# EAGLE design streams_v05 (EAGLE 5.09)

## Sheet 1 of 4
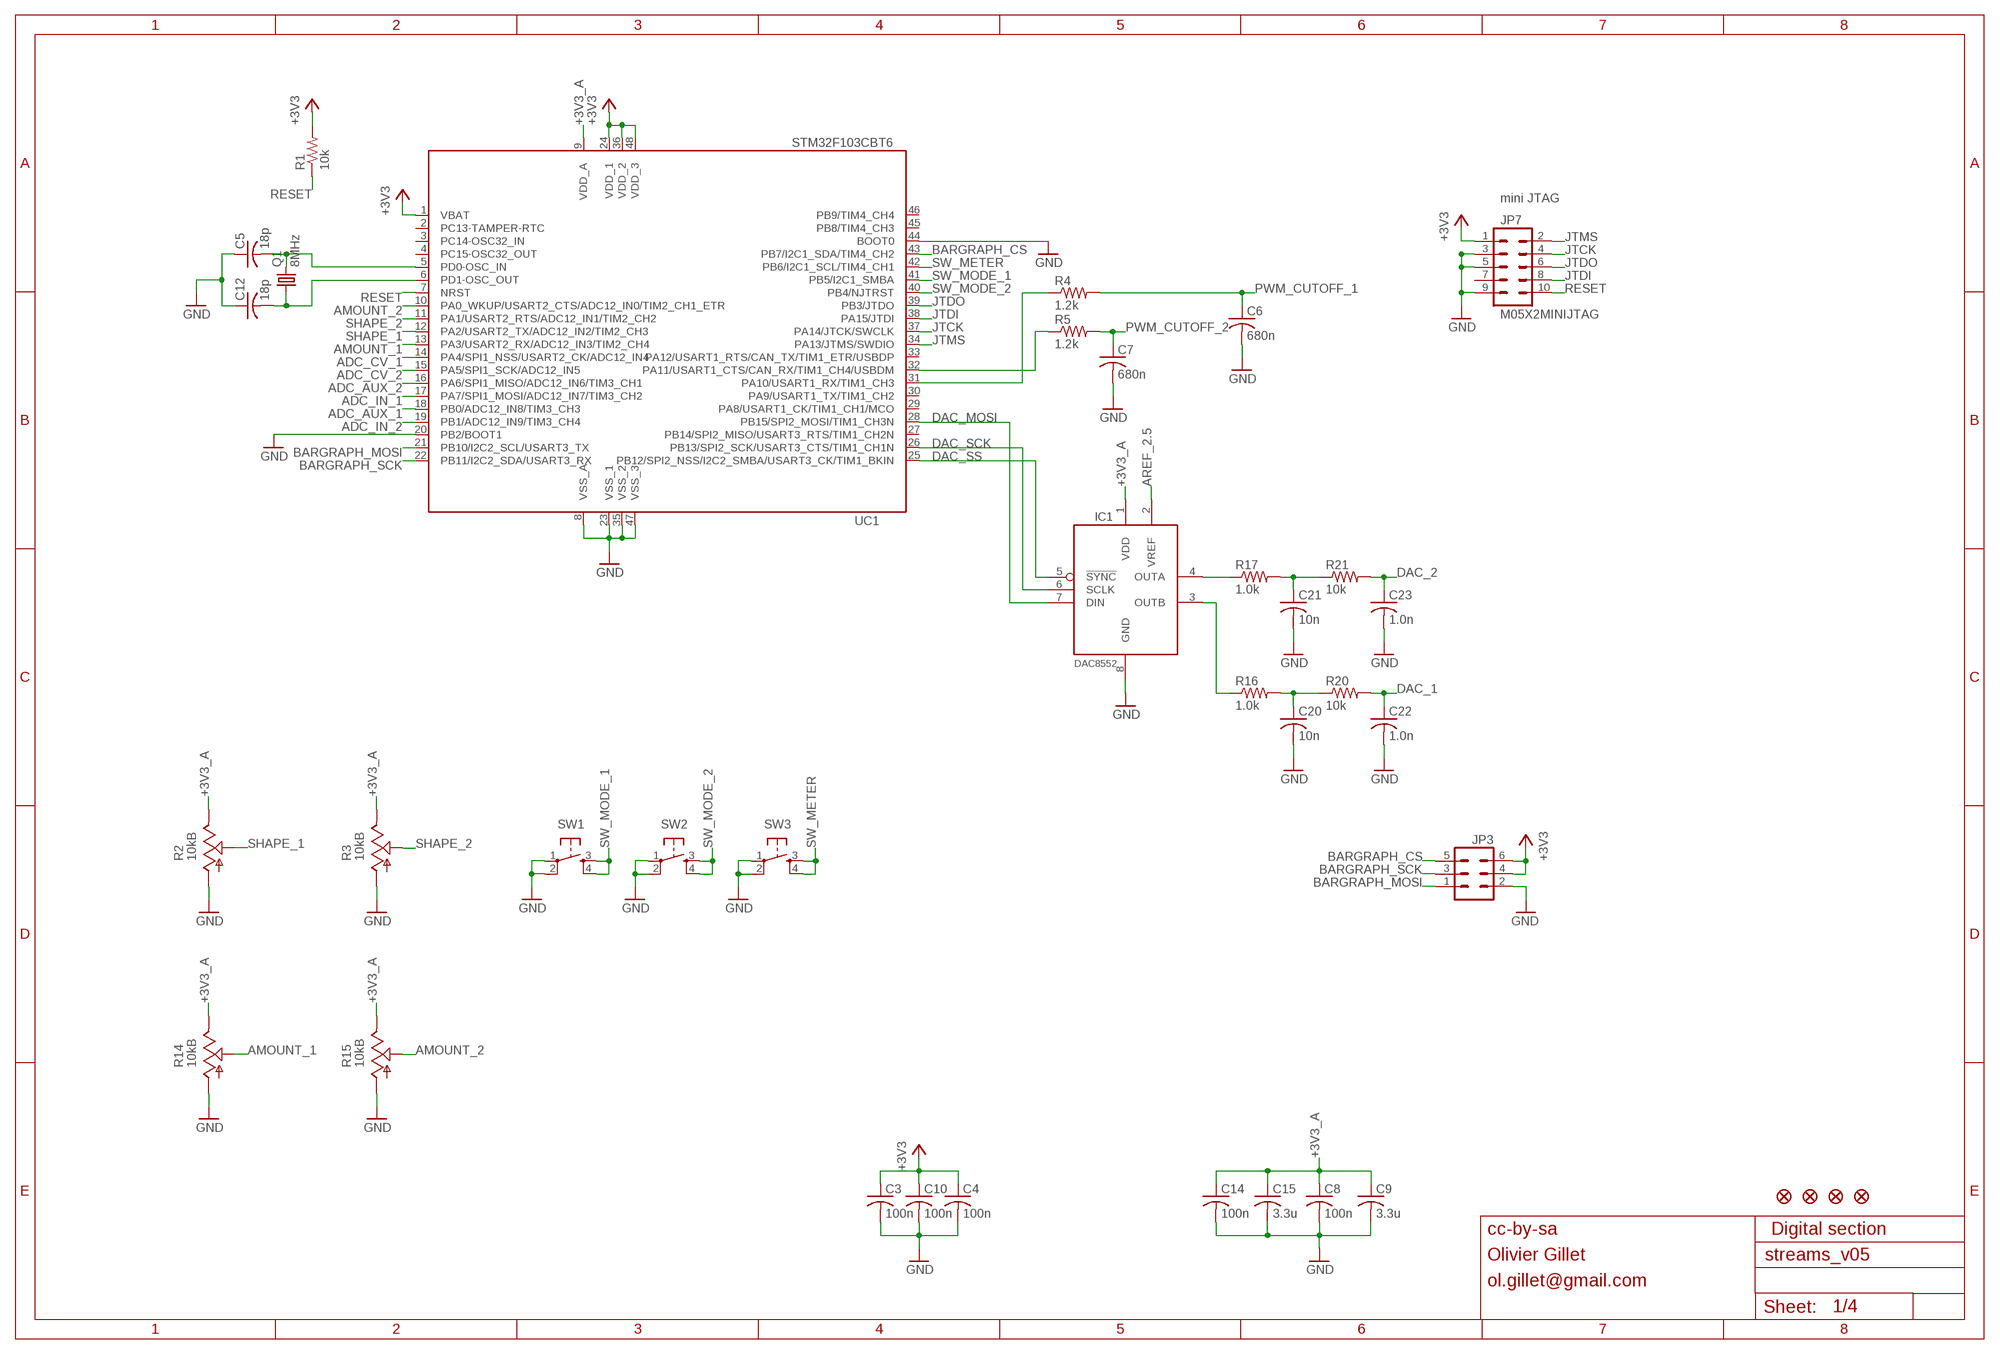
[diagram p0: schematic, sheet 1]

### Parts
C3  100n  C-USC0603  [C0603]
C4  100n  C-USC0603  [C0603]
C5  18p  C-USC0603  [C0603]
C6  680n  C-USC0603  [C0603]
C7  680n  C-USC0603  [C0603]
C8  100n  C-USC0603  [C0603]
C9  3.3u  C-USC0603  [C0603]
C10  100n  C-USC0603  [C0603]
C12  18p  C-USC0603  [C0603]
C14  100n  C-USC0603  [C0603]
C15  3.3u  C-USC0603  [C0603]
C20  10n  C-USC0603  [C0603]
C21  10n  C-USC0603  [C0603]
C22  1.0n  C-USC0603  [C0603]
C23  1.0n  C-USC0603  [C0603]
IC1  DAC8552  [MSOP-8]
JP1  FIDUCIAL1X2  [FIDUCIAL-1X2]
JP2  FIDUCIAL1X2  [FIDUCIAL-1X2]
JP3  M03X2BOTTOM  [2X3_BOTTOM]
JP4  FIDUCIAL1X2  [FIDUCIAL-1X2]
JP5  FIDUCIAL1X2  [FIDUCIAL-1X2]
JP7  M05X2MINIJTAG  [2X5-1.27]
Q1  8MHz  CRYSTALHC49UP  [HC49UP]
R1  10k  R-US_R0603  [R0603]
R2  10kB  POT_USVERTICAL_PS  [ALPS_POT_VERTICAL_PS]
R3  10kB  POT_USVERTICAL_PS  [ALPS_POT_VERTICAL_PS]
R4  1.2k  R-US_R0603  [R0603]
R5  1.2k  R-US_R0603  [R0603]
R14  10kB  POT_USVERTICAL_PS  [ALPS_POT_VERTICAL_PS]
R15  10kB  POT_USVERTICAL_PS  [ALPS_POT_VERTICAL_PS]
R16  1.0k  R-US_R0603  [R0603]
R17  1.0k  R-US_R0603  [R0603]
R20  10k  R-US_R0603  [R0603]
R21  10k  R-US_R0603  [R0603]
SW1  TAC_SWITCHPTH  [TACTILE-PTH]
SW2  TAC_SWITCHPTH  [TACTILE-PTH]
SW3  TAC_SWITCHPTH  [TACTILE-PTH]
UC1  STM32F103CBT6  STM32F103CB  [LQFP48]

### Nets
+3V3: C3.1 C4.1 C10.1 JP3.4 JP3.6 JP7.1 R1.2 UC1.1(VBAT) UC1.24(VDD_1) UC1.36(VDD_2) UC1.48(VDD_3) ; also sheet 4
+3V3_A: C8.1 C9.1 C14.1 C15.1 IC1.1(VDD) R2.P$1(E) R3.P$1(E) R14.P$1(E) R15.P$1(E) UC1.9(VDD_A) ; also sheet 2,3,4
ADC_AUX_1: UC1.18(PB0/ADC12_IN8/TIM3_CH3) ; also sheet 2
ADC_AUX_2: UC1.16(PA6/SPI1_MISO/ADC12_IN6/TIM3_CH1) ; also sheet 3
ADC_CV_1: UC1.14(PA4/SPI1_NSS/USART2_CK/ADC12_IN4) ; also sheet 2
ADC_CV_2: UC1.15(PA5/SPI1_SCK/ADC12_IN5) ; also sheet 3
ADC_IN_1: UC1.17(PA7/SPI1_MOSI/ADC12_IN7/TIM3_CH2) ; also sheet 2
ADC_IN_2: UC1.19(PB1/ADC12_IN9/TIM3_CH4) ; also sheet 3
AMOUNT_1: R14.P$2(S) UC1.13(PA3/USART2_RX/ADC12_IN3/TIM2_CH4)
AMOUNT_2: R15.P$2(S) UC1.10(PA0_WKUP/USART2_CTS/ADC12_IN0/TIM2_CH1_ETR)
AREF_2.5: IC1.2(VREF) ; also sheet 4
BARGRAPH_CS: JP3.5 UC1.43(PB7/I2C1_SDA/TIM4_CH2)
BARGRAPH_MOSI: JP3.1 UC1.21(PB10/I2C2_SCL/USART3_TX)
BARGRAPH_SCK: JP3.3 UC1.22(PB11/I2C2_SDA/USART3_RX)
DAC_1: C22.1 R20.2 ; also sheet 2
DAC_2: C23.1 R21.2 ; also sheet 3
DAC_MOSI: IC1.7(DIN) UC1.28(PB15/SPI2_MOSI/TIM1_CH3N)
DAC_SCK: IC1.6(SCLK) UC1.26(PB13/SPI2_SCK/USART3_CTS/TIM1_CH1N)
DAC_SS: IC1.5(!SYNC) UC1.25(PB12/SPI2_NSS/I2C2_SMBA/USART3_CK/TIM1_BKIN)
GND: C3.2 C4.2 C5.1 C6.2 C7.2 C8.2 C9.2 C10.2 C12.1 C14.2 C15.2 C20.2 C21.2 C22.2 C23.2 IC1.8(GND) JP3.2 JP7.3 JP7.5 JP7.9 R2.P$3(A) R3.P$3(A) R14.P$3(A) R15.P$3(A) SW1.1 SW1.2 SW2.1 SW2.2 SW3.1 SW3.2 UC1.8(VSS_A) UC1.20(PB2/BOOT1) UC1.23(VSS_1) UC1.35(VSS_2) UC1.44(BOOT0) UC1.47(VSS_3) ; also sheet 2,3,4
JTCK: JP7.4 UC1.37(PA14/JTCK/SWCLK)
JTDI: JP7.8 UC1.38(PA15/JTDI)
JTDO: JP7.6 UC1.39(PB3/JTDO)
JTMS: JP7.2 UC1.34(PA13/JTMS/SWDIO)
N$7: C5.2 Q1.2 UC1.5(PD0-OSC_IN)
N$8: C12.2 Q1.1 UC1.6(PD1-OSC_OUT)
N$70: IC1.4(OUTA) R17.1
N$72: IC1.3(OUTB) R16.1
N$73: C21.1 R17.2 R21.1
N$74: C20.1 R16.2 R20.1
N$90: R5.1 UC1.32(PA11/USART1_CTS/CAN_RX/TIM1_CH4/USBDM)
N$93: R4.1 UC1.31(PA10/USART1_RX/TIM1_CH3)
PWM_CUTOFF_1: C6.1 R4.2 ; also sheet 2
PWM_CUTOFF_2: C7.1 R5.2 ; also sheet 3
RESET: JP7.10 R1.1 UC1.7(NRST)
SHAPE_1: R2.P$2(S) UC1.12(PA2/USART2_TX/ADC12_IN2/TIM2_CH3)
SHAPE_2: R3.P$2(S) UC1.11(PA1/USART2_RTS/ADC12_IN1/TIM2_CH2)
SW_METER: SW3.3 SW3.4 UC1.42(PB6/I2C1_SCL/TIM4_CH1)
SW_MODE_1: SW1.3 SW1.4 UC1.41(PB5/I2C1_SMBA)
SW_MODE_2: SW2.3 SW2.4 UC1.40(PB4/NJTRST)
Unconnected: JP7.7 UC1.2(PC13-TAMPER-RTC) UC1.3(PC14-OSC32_IN) UC1.4(PC15-OSC32_OUT) UC1.27(PB14/SPI2_MISO/USART3_RTS/TIM1_CH2N) UC1.29(PA8/USART1_CK/TIM1_CH1/MCO) UC1.30(PA9/USART1_TX/TIM1_CH2) UC1.33(PA12/USART1_RTS/CAN_TX/TIM1_ETR/USBDP) UC1.45(PB8/TIM4_CH3) UC1.46(PB9/TIM4_CH4)

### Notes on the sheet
- mini JTAG
- cc-by-sa | Digital section
- Olivier Gillet
- ol.gillet@gmail.com

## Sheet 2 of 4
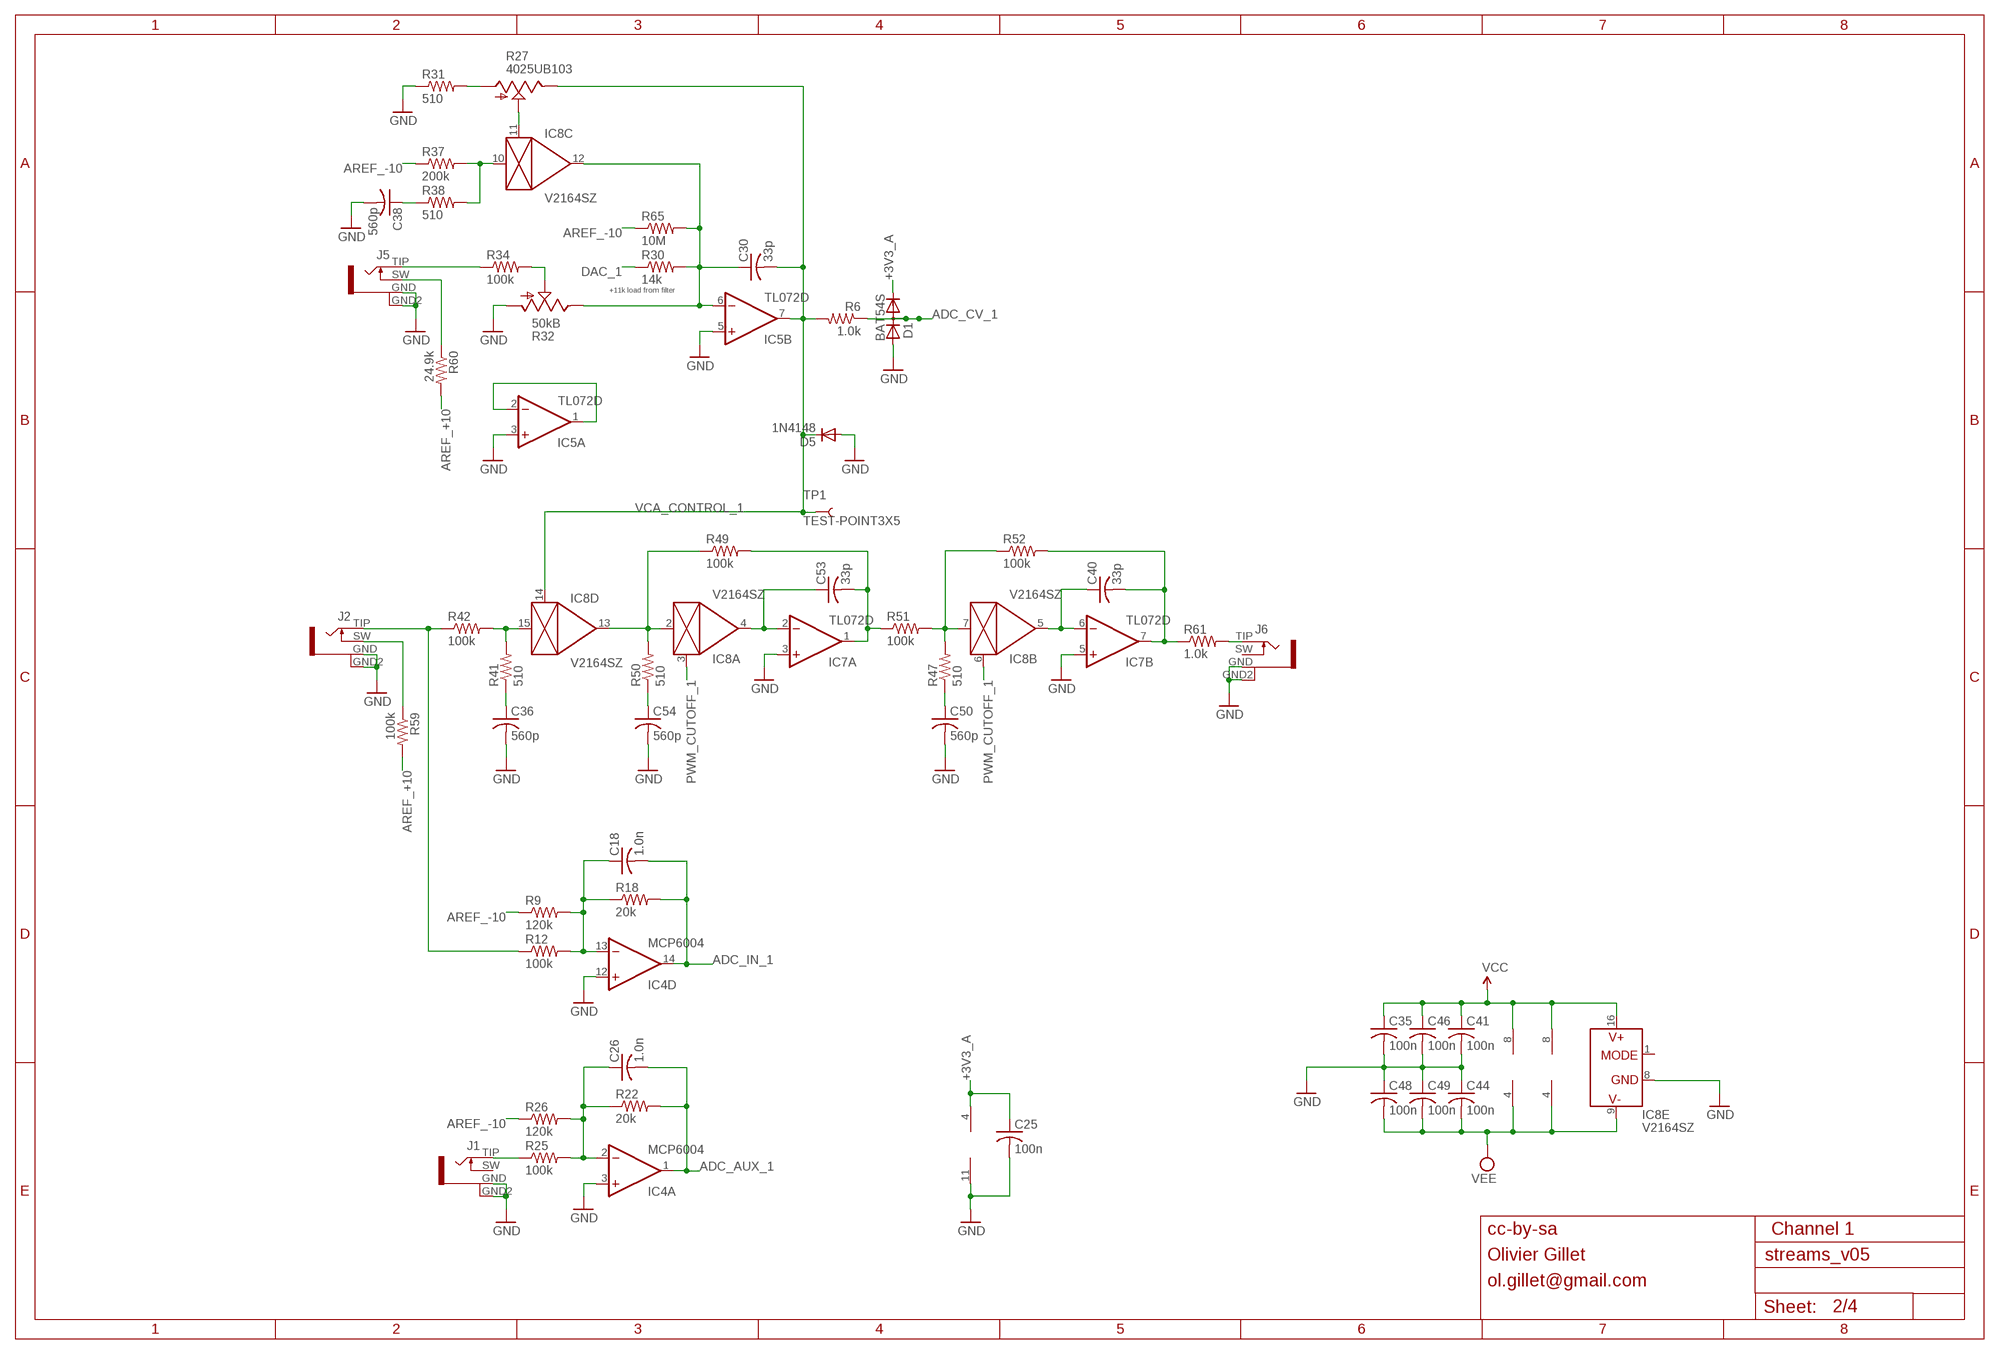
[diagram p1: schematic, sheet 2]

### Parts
C18  1.0n  C-USC0603  [C0603]
C25  100n  C-USC0603  [C0603]
C26  1.0n  C-USC0603  [C0603]
C30  33p  C-USC0603  [C0603]
C35  100n  C-USC0603  [C0603]
C36  560p  C-USC0603  [C0603]
C38  560p  C-USC0603  [C0603]
C40  33p  C-USC0603  [C0603]
C41  100n  C-USC0603  [C0603]
C44  100n  C-USC0603  [C0603]
C46  100n  C-USC0603  [C0603]
C48  100n  C-USC0603  [C0603]
C49  100n  C-USC0603  [C0603]
C50  560p  C-USC0603  [C0603]
C53  33p  C-USC0603  [C0603]
C54  560p  C-USC0603  [C0603]
D1  BAT54S  DIODE_2CACA-SOT23  [SOT23]
D5  1N4148  DIODE-SOD323-W  [SOD323-W]
IC4  MCP6004  TL074D  [SO14]
IC5  TL072D  [SO08]
IC7  TL072D  [SO08]
IC8  V2164SZ  SSM2164S  [SOIC16N]
J1  PJ301WQP  [WQP_PJ_301BM_WIDER]
J2  PJ301WQP  [WQP_PJ_301BM_WIDER]
J5  PJ301WQP  [WQP_PJ_301BM_WIDER]
J6  PJ301WQP  [WQP_PJ_301BM_WIDER]
R6  1.0k  R-US_R0603  [R0603]
R9  120k  R-US_R0603  [R0603]
R12  100k  R-US_R0603  [R0603]
R18  20k  R-US_R0603  [R0603]
R22  20k  R-US_R0603  [R0603]
R25  100k  R-US_R0603  [R0603]
R26  120k  R-US_R0603  [R0603]
R27  4025UB103  POT_USVERTICAL  [ALPS_POT_VERTICAL]
R30  14k  R-US_R0603  [R0603]
R31  510  R-US_R0603  [R0603]
R32  50kB  POT_USVERTICAL_PS  [ALPS_POT_VERTICAL_PS]
R34  100k  R-US_R0603  [R0603]
R37  200k  R-US_R0603  [R0603]
R38  510  R-US_R0603  [R0603]
R41  510  R-US_R0603  [R0603]
R42  100k  R-US_R0603  [R0603]
R47  510  R-US_R0603  [R0603]
R49  100k  R-US_R0603  [R0603]
R50  510  R-US_R0603  [R0603]
R51  100k  R-US_R0603  [R0603]
R52  100k  R-US_R0603  [R0603]
R59  100k  R-US_R0603  [R0603]
R60  24.9k  R-US_R0603  [R0603]
R61  1.0k  R-US_R0603  [R0603]
R65  10M  R-US_R0603  [R0603]
TP1  TEST-POINT3X5  [PAD.03X.05]

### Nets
+3V3_A: C25.1 D1.2(C) IC4.4(P:V+) ; also sheet 1,3,4
ADC_AUX_1: C26.2 IC4.1(A:OUT) R22.2 ; also sheet 1
ADC_CV_1: D1.3(AC) R6.1 ; also sheet 1
ADC_IN_1: C18.2 IC4.14(D:OUT) R18.2 ; also sheet 1
AREF_+5: J2.SW R59.1
AREF_+10: R59.2 R60.2 ; also sheet 3,4
AREF_-10: R9.1 R26.1 R37.1 R65.1 ; also sheet 3,4
DAC_1: R30.1 ; also sheet 1
FB_CURRENT1: IC8.10(C:IN) R37.2 R38.2
FB_CURRENT2: IC8.15(D:IN) R41.2 R42.2
GND: C25.2 C35.2 C36.2 C38.2 C41.2 C44.1 C46.2 C48.1 C49.1 C50.2 C54.2 D1.1(A) D5.A IC4.3(A:+IN) IC4.11(P:V-) IC4.12(D:+IN) IC5.3(A:+IN) IC5.5(B:+IN) IC7.3(A:+IN) IC7.5(B:+IN) IC8.8(E:GND) J1.GND J1.GND2 J2.GND J2.GND2 J5.GND J5.GND2 J6.GND J6.GND2 R31.1 R32.P$3(A) ; also sheet 1,3,4
IN_1: J2.TIP R12.1 R42.1
N$1: R27.P$3(A) R31.2
N$2: C30.1 IC5.6(B:-IN) IC8.12(C:OUT) R30.2 R32.P$1(E) R65.2
N$5: C38.1 R38.1
N$10: C36.1 R41.1
N$11: IC5.1(A:OUT) IC5.2(A:-IN)
N$12: J5.SW R60.1
N$13: J5.TIP R34.1
N$15: IC8.11(C:CTRL) R27.P$2(S)
N$23: R32.P$2(S) R34.2
N$26: C40.1 IC7.6(B:-IN) IC8.5(B:OUT)
N$27: C40.2 IC7.7(B:OUT) R52.2 R61.1
N$51: IC8.2(A:IN) IC8.13(D:OUT) R49.1 R50.2
N$65: J1.TIP R25.1
N$68: C18.1 IC4.13(D:-IN) R9.2 R12.2 R18.1
N$69: C26.1 IC4.2(A:-IN) R22.1 R25.2 R26.2
N$79: C53.1 IC7.2(A:-IN) IC8.4(A:OUT)
N$83: C53.2 IC7.1(A:OUT) R49.2 R51.1
N$84: IC8.7(B:IN) R47.2 R51.2 R52.1
N$85: C54.1 R50.1
N$86: C50.1 R47.1
N$87: J6.TIP R61.2
PWM_CUTOFF_1: IC8.3(A:CTRL) IC8.6(B:CTRL) ; also sheet 1
VCA_CONTROL_1: C30.2 D5.C IC5.7(B:OUT) IC8.14(D:CTRL) R6.2 R27.P$1(E) TP1.P$1
VCC: C35.1 C41.1 C46.1 IC5.8(P:V+) IC7.8(P:V+) IC8.16(E:V+) ; also sheet 3,4
VEE: C44.2 C48.2 C49.2 IC5.4(P:V-) IC7.4(P:V-) IC8.9(E:V-) ; also sheet 3,4
Unconnected: IC8.1(E:MODE) J1.SW J6.SW

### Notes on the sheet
- +11k load from filter
- cc-by-sa | Channel 1
- Olivier Gillet
- ol.gillet@gmail.com

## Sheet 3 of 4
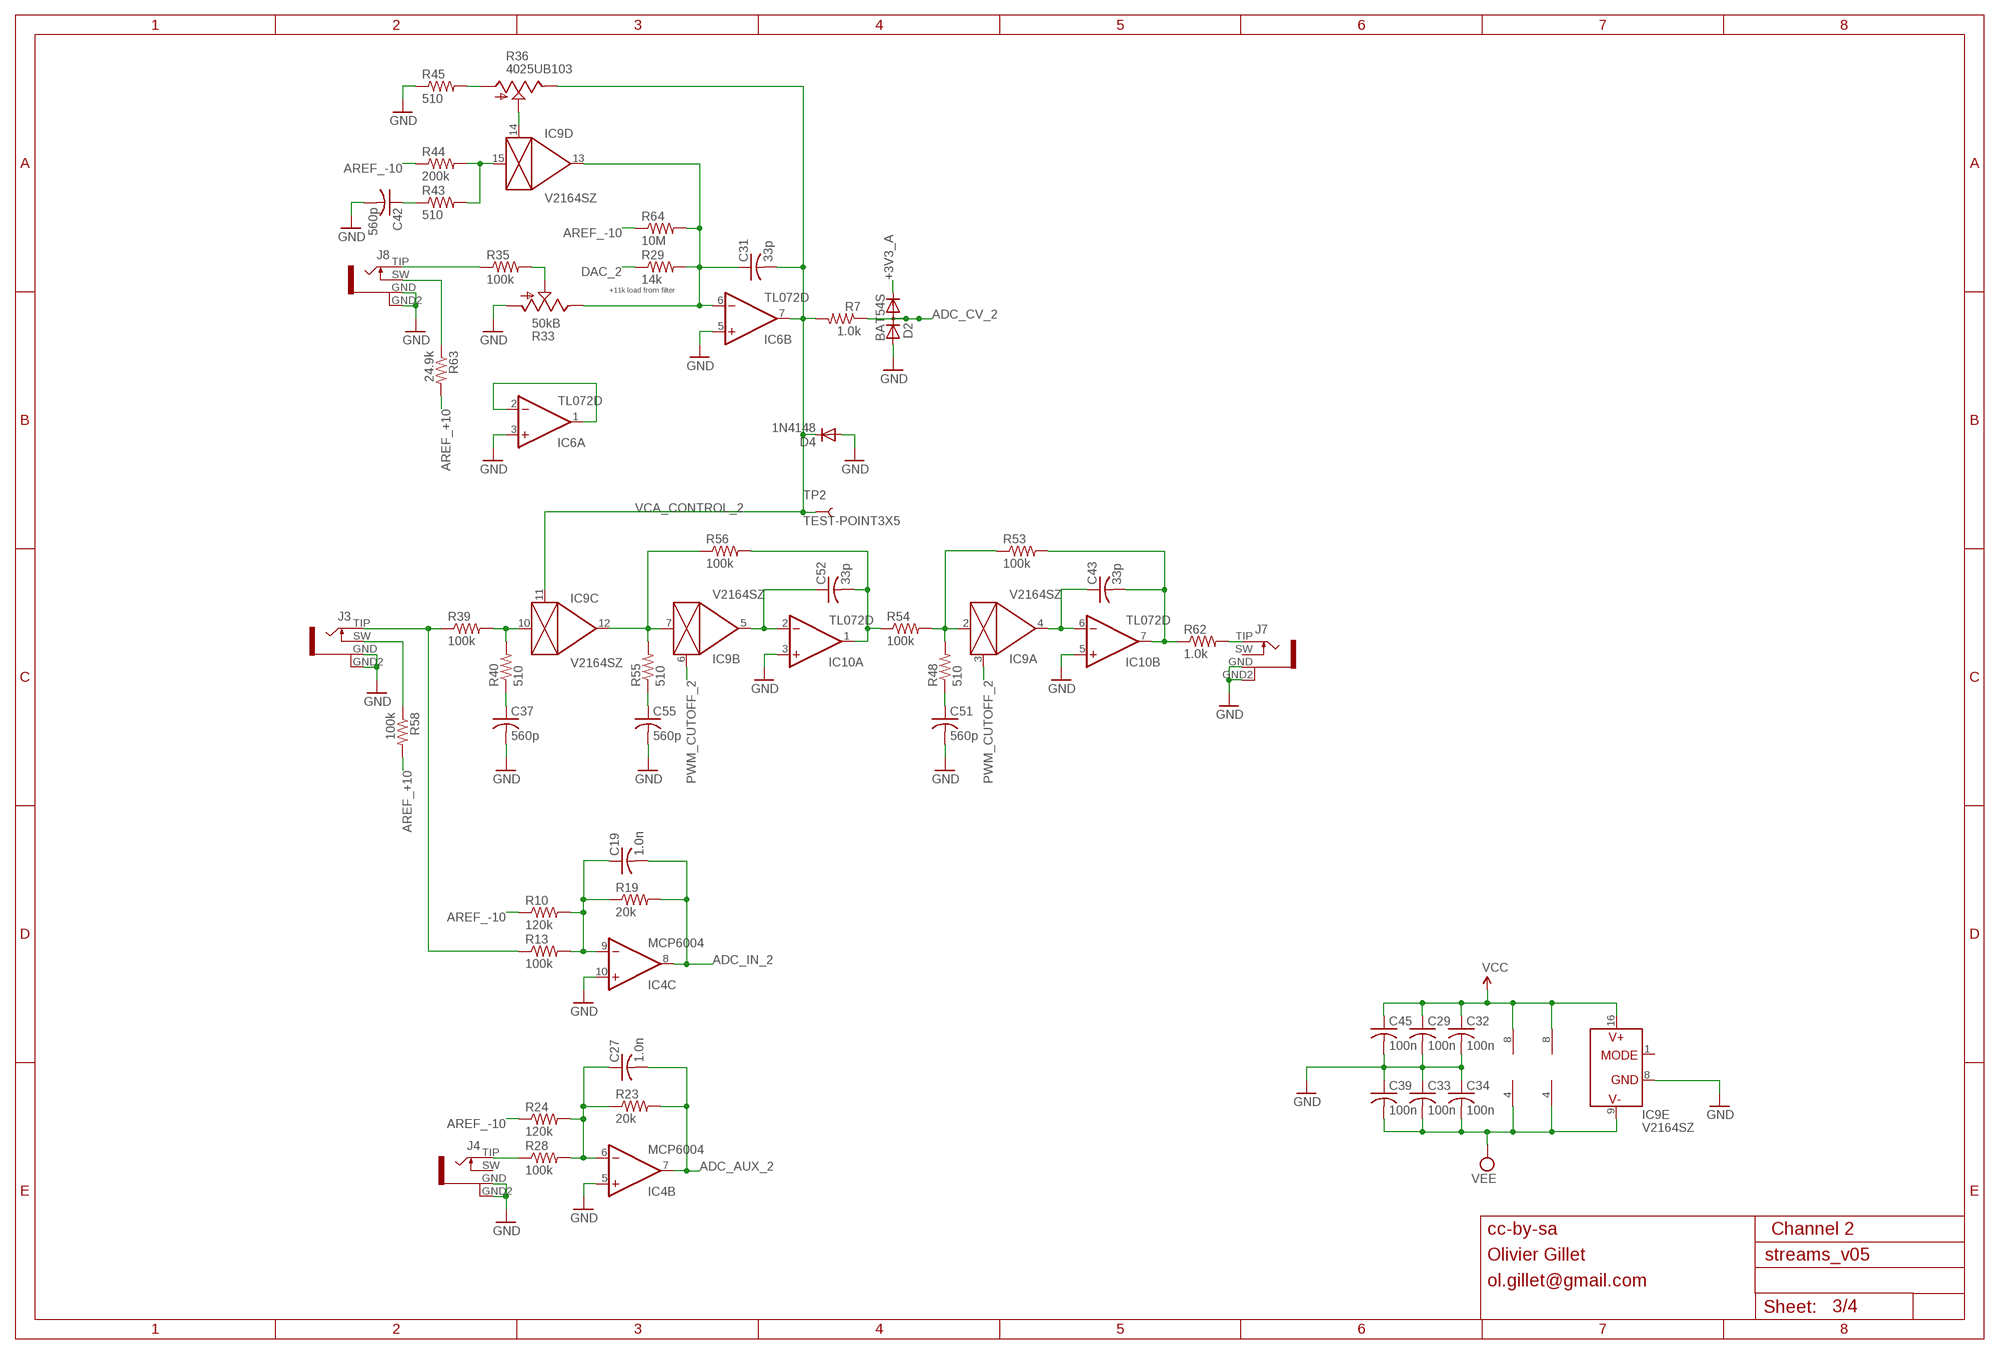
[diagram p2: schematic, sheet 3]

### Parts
C19  1.0n  C-USC0603  [C0603]
C27  1.0n  C-USC0603  [C0603]
C29  100n  C-USC0603  [C0603]
C31  33p  C-USC0603  [C0603]
C32  100n  C-USC0603  [C0603]
C33  100n  C-USC0603  [C0603]
C34  100n  C-USC0603  [C0603]
C37  560p  C-USC0603  [C0603]
C39  100n  C-USC0603  [C0603]
C42  560p  C-USC0603  [C0603]
C43  33p  C-USC0603  [C0603]
C45  100n  C-USC0603  [C0603]
C51  560p  C-USC0603  [C0603]
C52  33p  C-USC0603  [C0603]
C55  560p  C-USC0603  [C0603]
D2  BAT54S  DIODE_2CACA-SOT23  [SOT23]
D4  1N4148  DIODE-SOD323-W  [SOD323-W]
IC6  TL072D  [SO08]
IC9  V2164SZ  SSM2164S  [SOIC16N]
IC10  TL072D  [SO08]
J3  PJ301WQP  [WQP_PJ_301BM_WIDER]
J4  PJ301WQP  [WQP_PJ_301BM_WIDER]
J7  PJ301WQP  [WQP_PJ_301BM_WIDER]
J8  PJ301WQP  [WQP_PJ_301BM_WIDER]
R7  1.0k  R-US_R0603  [R0603]
R10  120k  R-US_R0603  [R0603]
R13  100k  R-US_R0603  [R0603]
R19  20k  R-US_R0603  [R0603]
R23  20k  R-US_R0603  [R0603]
R24  120k  R-US_R0603  [R0603]
R28  100k  R-US_R0603  [R0603]
R29  14k  R-US_R0603  [R0603]
R33  50kB  POT_USVERTICAL_PS  [ALPS_POT_VERTICAL_PS]
R35  100k  R-US_R0603  [R0603]
R36  4025UB103  POT_USVERTICAL  [ALPS_POT_VERTICAL]
R39  100k  R-US_R0603  [R0603]
R40  510  R-US_R0603  [R0603]
R43  510  R-US_R0603  [R0603]
R44  200k  R-US_R0603  [R0603]
R45  510  R-US_R0603  [R0603]
R48  510  R-US_R0603  [R0603]
R53  100k  R-US_R0603  [R0603]
R54  100k  R-US_R0603  [R0603]
R55  510  R-US_R0603  [R0603]
R56  100k  R-US_R0603  [R0603]
R58  100k  R-US_R0603  [R0603]
R62  1.0k  R-US_R0603  [R0603]
R63  24.9k  R-US_R0603  [R0603]
R64  10M  R-US_R0603  [R0603]
TP2  TEST-POINT3X5  [PAD.03X.05]

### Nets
+3V3_A: D2.2(C) ; also sheet 1,2,4
ADC_AUX_2: C27.2 IC4.7(B:OUT) R23.2 ; also sheet 1
ADC_CV_2: D2.3(AC) R7.1 ; also sheet 1
ADC_IN_2: C19.2 IC4.8(C:OUT) R19.2 ; also sheet 1
AREF_+10: R58.2 R63.2 ; also sheet 2,4
AREF_-10: R10.1 R24.1 R44.1 R64.1 ; also sheet 2,4
DAC_2: R29.1 ; also sheet 1
FB_CURRENT3: IC9.10(C:IN) R39.2 R40.2
FB_CURRENT4: IC9.15(D:IN) R43.2 R44.2
GND: C29.2 C32.2 C33.1 C34.1 C37.2 C39.1 C42.2 C45.2 C51.2 C55.2 D2.1(A) D4.A IC4.5(B:+IN) IC4.10(C:+IN) IC6.3(A:+IN) IC6.5(B:+IN) IC9.8(E:GND) IC10.3(A:+IN) IC10.5(B:+IN) J3.GND J3.GND2 J4.GND J4.GND2 J7.GND J7.GND2 J8.GND J8.GND2 R33.P$3(A) R45.1 ; also sheet 1,2,4
IN_2: J3.TIP R13.1 R39.1
N$3: J8.SW R63.1
N$4: C37.1 R40.1
N$9: C31.1 IC6.6(B:-IN) IC9.13(D:OUT) R29.2 R33.P$1(E) R64.2
N$14: C43.1 IC9.4(A:OUT) IC10.6(B:-IN)
N$16: C43.2 IC10.7(B:OUT) R53.2 R62.1
N$17: J7.TIP R62.2
N$18: R36.P$3(A) R45.2
N$19: C42.1 R43.1
N$24: R33.P$2(S) R35.2
N$25: J8.TIP R35.1
N$28: IC6.1(A:OUT) IC6.2(A:-IN)
N$29: IC9.14(D:CTRL) R36.P$2(S)
N$43: J3.SW R58.1
N$66: C27.1 IC4.6(B:-IN) R23.1 R24.2 R28.2
N$67: J4.TIP R28.1
N$71: C19.1 IC4.9(C:-IN) R10.2 R13.2 R19.1
N$75: IC9.7(B:IN) IC9.12(C:OUT) R55.2 R56.1
N$76: C52.1 IC9.5(B:OUT) IC10.2(A:-IN)
N$77: IC9.2(A:IN) R48.2 R53.1 R54.2
N$78: C52.2 IC10.1(A:OUT) R54.1 R56.2
N$81: C55.1 R55.1
N$82: C51.1 R48.1
PWM_CUTOFF_2: IC9.3(A:CTRL) IC9.6(B:CTRL) ; also sheet 1
VCA_CONTROL_2: C31.2 D4.C IC6.7(B:OUT) IC9.11(C:CTRL) R7.2 R36.P$1(E) TP2.P$1
VCC: C29.1 C32.1 C45.1 IC6.8(P:V+) IC9.16(E:V+) IC10.8(P:V+) ; also sheet 2,4
VEE: C33.2 C34.2 C39.2 IC6.4(P:V-) IC9.9(E:V-) IC10.4(P:V-) ; also sheet 2,4
Unconnected: IC9.1(E:MODE) J4.SW J7.SW

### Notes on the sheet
- +11k load from filter
- cc-by-sa | Channel 2
- Olivier Gillet
- ol.gillet@gmail.com

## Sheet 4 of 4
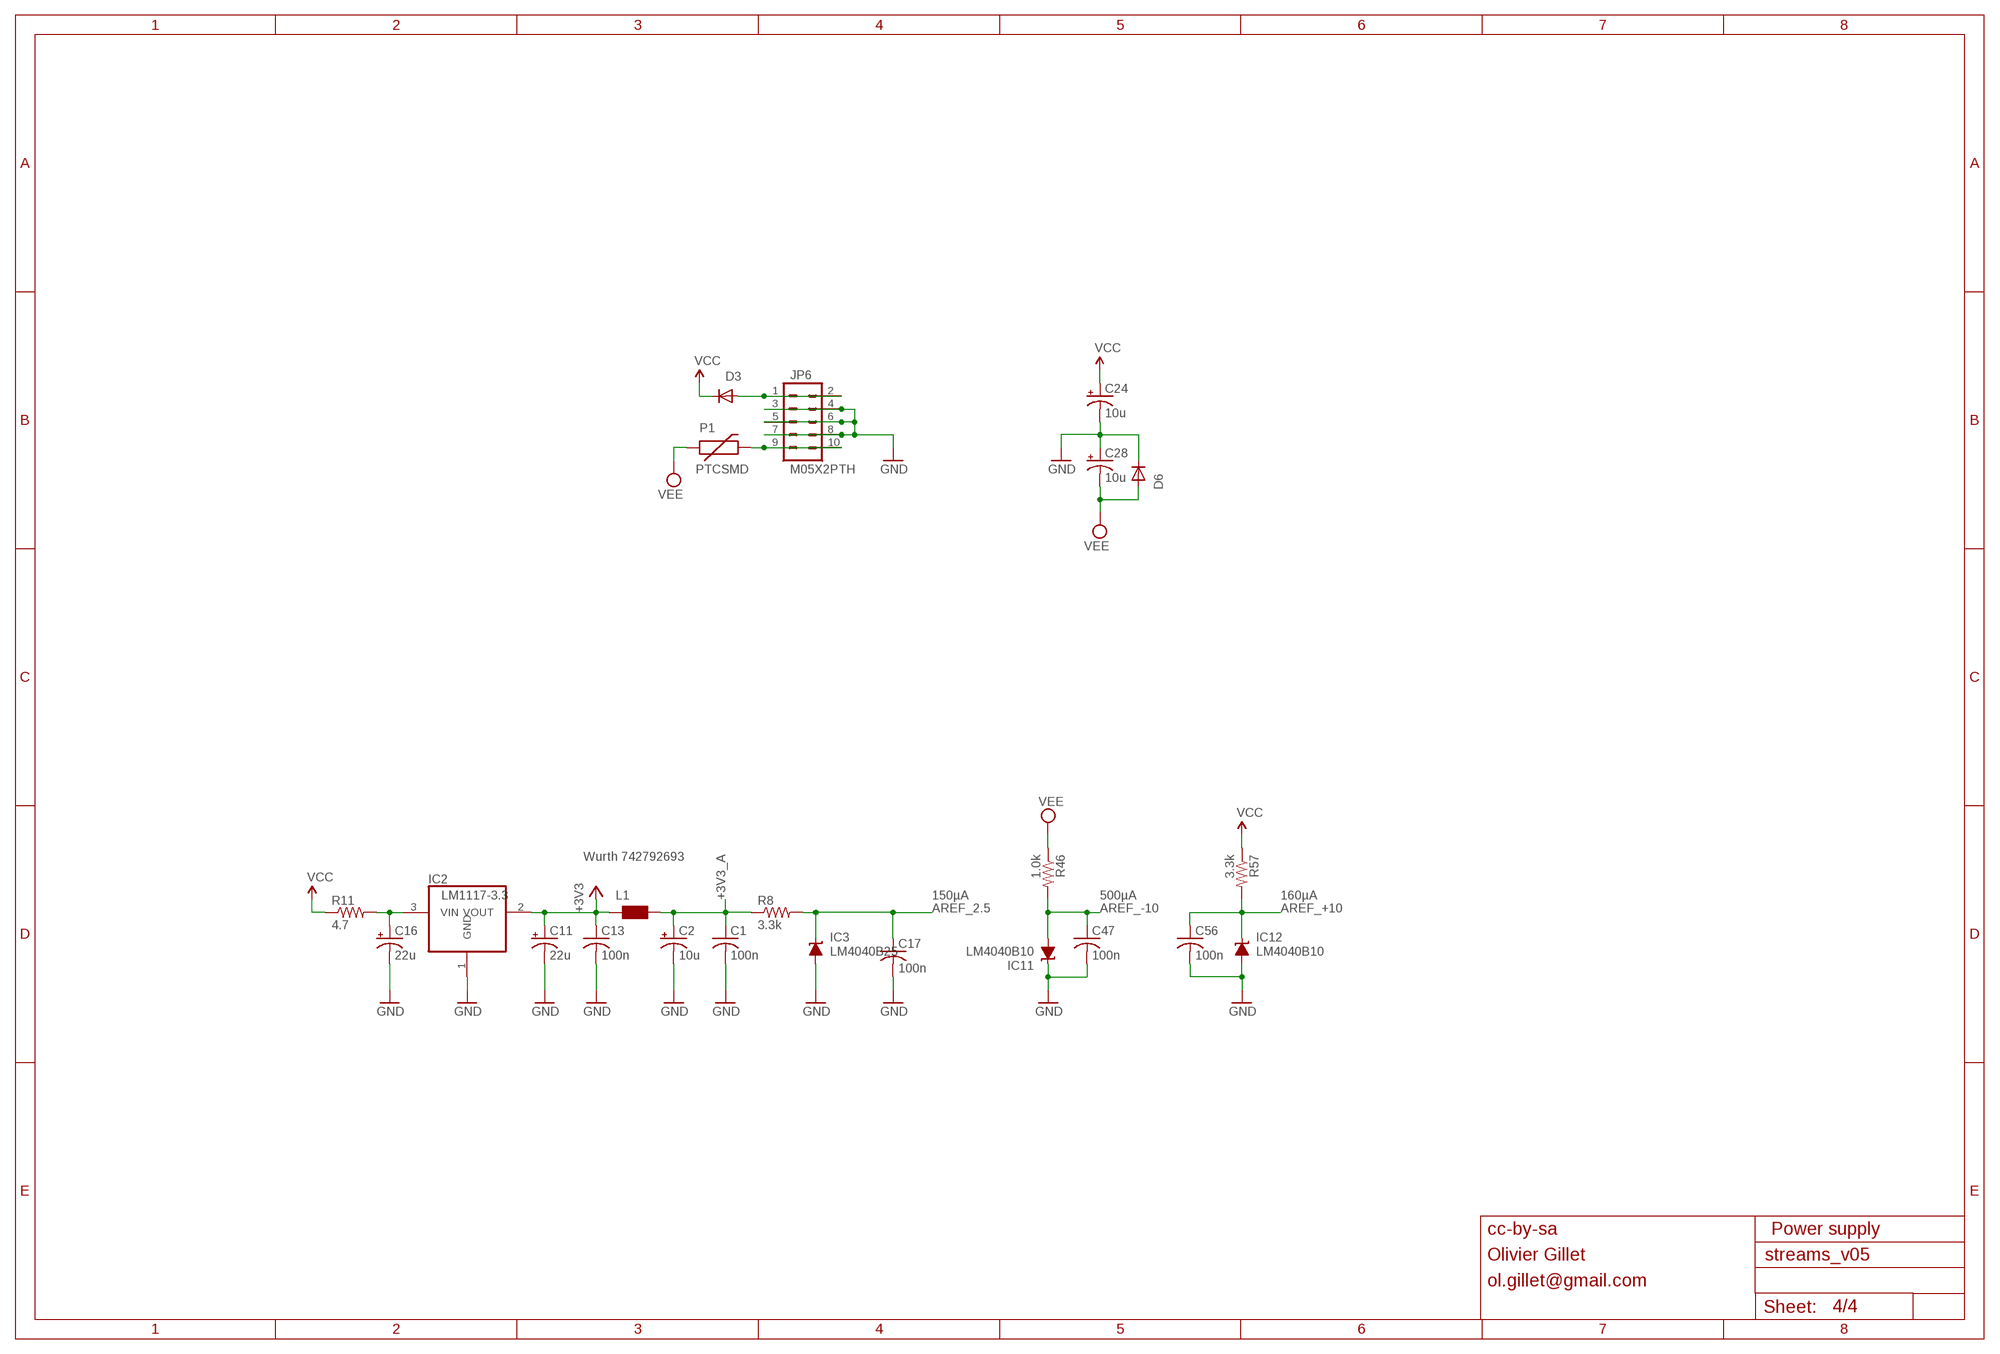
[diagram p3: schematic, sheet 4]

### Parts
C1  100n  C-USC0603  [C0603]
C2  10u  CPOL-USB  [PANASONIC_B]
C11  22u  CPOL-USB  [PANASONIC_B]
C13  100n  C-USC0603  [C0603]
C16  22u  CPOL-USC  [PANASONIC_C]
C17  100n  C-USC0603  [C0603]
C24  10u  CPOL-USB  [PANASONIC_B]
C28  10u  CPOL-USB  [PANASONIC_B]
C47  100n  C-USC0603  [C0603]
C56  100n  C-USC0603  [C0603]
D3  1N5819HW  DIODE-SOD123  [SOD123]
D6  1N5819HW  DIODE-SOD123  [SOD123]
IC2  LM1117-3.3  REG1117  [SOT223]
IC3  LM4040B25  LM4041B12DBZ  [DBZ_R-PDSO-G3]
IC11  LM4040B10  LM4041B12DBZ  [DBZ_R-PDSO-G3]
IC12  LM4040B10  LM4041B12DBZ  [DBZ_R-PDSO-G3]
JP6  M05X2PTH  [AVR_ICSP]
L1  WE-CBF_0603  [0603]
P1  PTCSMD  [PTC-1206]
R8  3.3k  R-US_R0603  [R0603]
R11  4.7  R-US_R1206  [R1206]
R46  1.0k  R-US_R0603  [R0603]
R57  3.3k  R-US_R0603  [R0603]

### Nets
+3V3: C11.+ C13.1 IC2.2(VOUT) L1.1 ; also sheet 1
+3V3_A: C1.1 C2.+ L1.2 R8.1 ; also sheet 1,2,3
AREF_2.5: C17.1 IC3.1(C) R8.2 ; also sheet 1
AREF_+10: C56.1 IC12.1(C) R57.2 ; also sheet 2,3
AREF_-10: C47.1 IC11.2(A) R46.2 ; also sheet 2,3
GND: C1.2 C2.- C11.- C13.2 C16.- C17.2 C24.- C28.+ C47.2 C56.2 D6.C IC2.1(GND) IC3.2(A) IC11.1(C) IC12.2(A) JP6.3 JP6.4 JP6.5 JP6.6 JP6.7 JP6.8 ; also sheet 1,2,3
N$21: C16.+ IC2.3(VIN) R11.2
N$56: D3.A JP6.1 JP6.2
N$64: JP6.9 JP6.10 P1.2
VCC: C24.+ D3.C R11.1 R57.1 ; also sheet 2,3
VEE: C28.- D6.A P1.1 R46.1 ; also sheet 2,3

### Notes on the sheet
- Wurth 742792693
- 150µA | 500µA | 160µA
- cc-by-sa | Power supply
- Olivier Gillet
- ol.gillet@gmail.com

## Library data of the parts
C1 C3-C10 C12-C15 C17-C23 C25-C27 C29-C56 = rcl:C-US: CAPACITOR, American symbol
C2 C11 C16 C24 C28 = rcl:CPOL-US: POLARIZED CAPACITOR, American symbol
D1 D2 = diode:DIODE_2CACA-: 2 Diodes - Cathode-Anode|Cathode-Anode
D3-D6 = diode:DIODE-: DIODE
IC1 = og-dac:DAC8552
IC2 = og-vreg:REG1117: 800mA and 1A Low Dropout (LDO) Positive Regulator 1.8V, 2.5V, 2.85V, 3.3V, 5V, and Adj
IC3 IC11 IC12 = texas:LM4041: PRECISION MICROPOWER SHUNT VOLTAGE REFERENCE
IC4 = gm-ics:TL074: OP AMP
IC5-IC7 IC10 = og-linear:TL072: OP AMP
IC8 IC9 = ssm2164:SSM2164
J1-J8 = og-pj301:PJ301
JP1 JP2 JP4 JP5 = SparkFun:FIDUCIAL: Fiducial Alignment Points
JP3 = og-header:M03X2: PIN HEADER
JP6 JP7 = og-header:M05X2: Header 5x2 Standard 10-pin dual row 0.1" header. Commonly used with AVR-ISP. Use with Spark Fun Electronics SKU: PRT-00778
L1 = wuerth-elektronik:WE-CBF: SMD EMI Suppression Ferrite Beads
P1 = SparkFun:PTC: Resettable Fuse PTC
Q1 = crystal:CRYSTAL: CRYSTAL
R1 R4-R13 R16-R26 R28-R31 R34 R35 R37-R65 = rcl:R-US_: RESISTOR, American symbol
R2 R3 R14 R15 R27 R32 R33 R36 = pot-alps:POT_US
SW1-SW3 = SparkFun:TAC_SWITCH: Momentary Switch Button commonly used for reset or general input. Spark Fun Electronics SKU : COM-00097
TP1 TP2 = SparkFun:TEST-POINT
UC1 = stm32:STM32F103CB

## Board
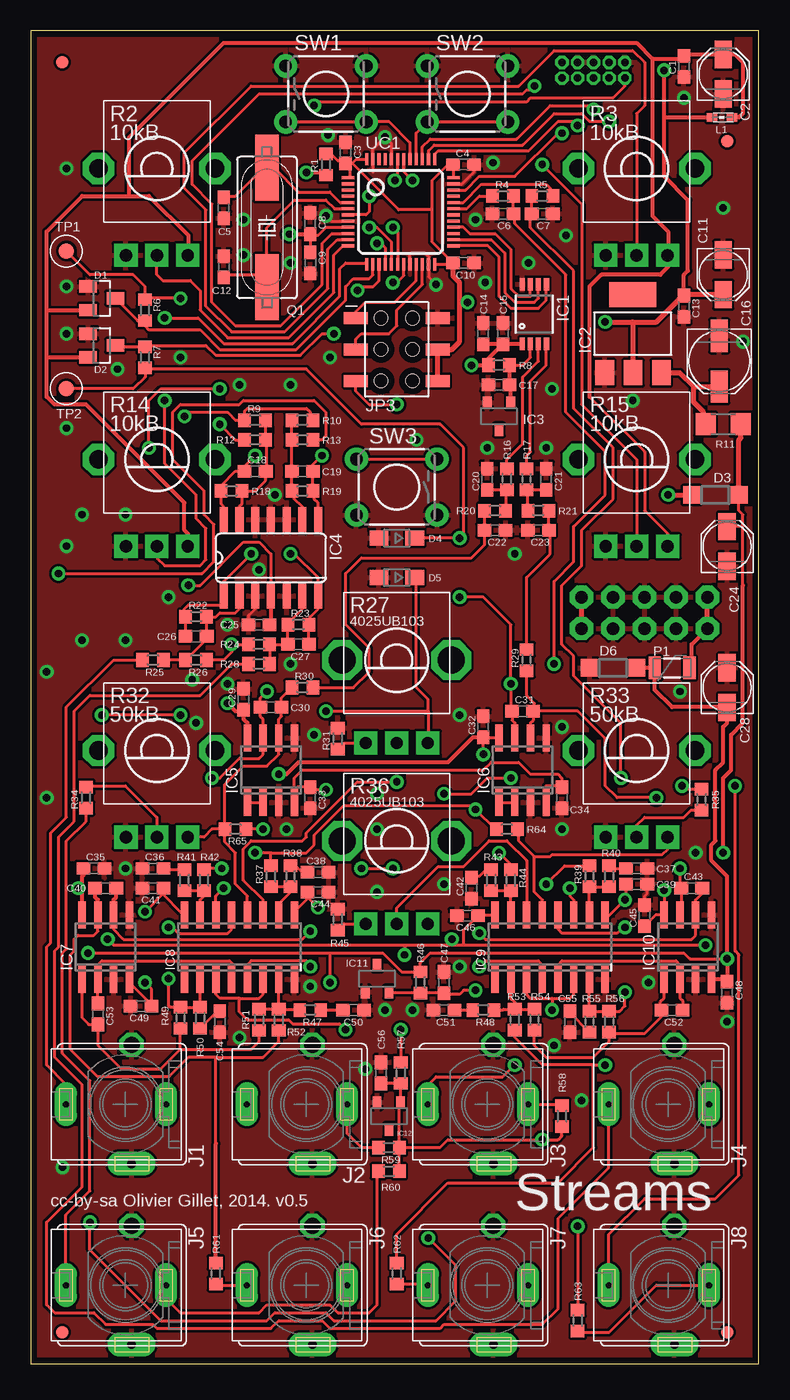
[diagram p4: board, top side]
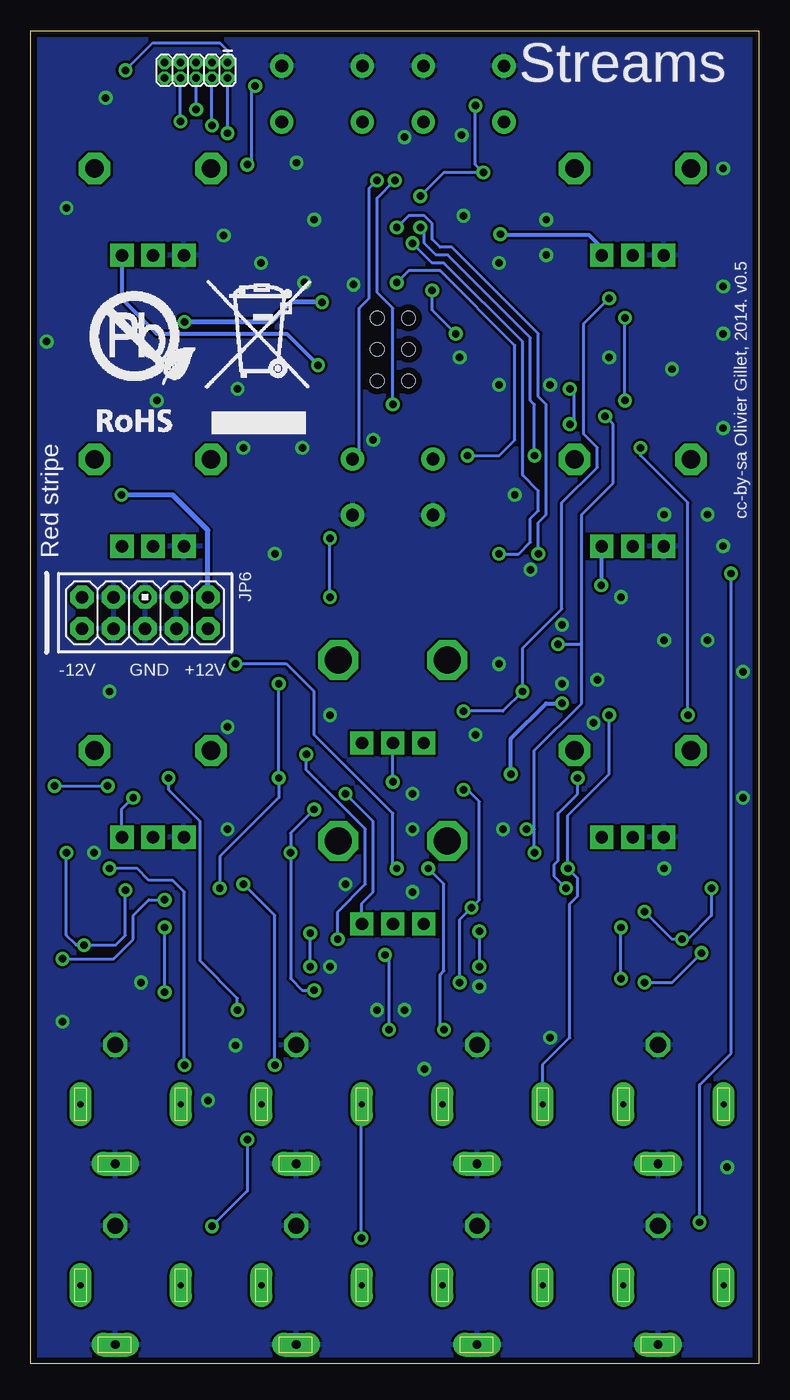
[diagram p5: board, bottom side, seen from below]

Size 58.74 x 107.63 mm. Coordinates in mm from the lower left corner, seen from the top.
Outline: 0,0 58.74,0 58.74,107.63 0,107.63 0,0
Copper layers (1*16): Top 0.035mm / dielectric 1.5mm / Bottom 0.035mm
Design rules "PCBCart-Standard": minimum track width 8mil, minimum drill 0.4mm, track to track 8mil, track to pad 8mil, pad to pad 8mil, via to via 8mil, smd to smd 8mil, copper to edge 20mil, drill to drill 8mil, minimum pad ring 8mil, minimum via ring 10mil, stop-mask expansion 3mil, vias tented up to drill 25mil, thermal gap 8mil

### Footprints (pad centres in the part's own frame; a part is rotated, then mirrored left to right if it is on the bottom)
C0603 = smd 1.1 x 1: 1 -0.85,0; 2 0.85,0
PANASONIC_B = smd 2.2 x 1.4: + 1.6,0; - -1.6,0
PANASONIC_C = smd 2.6 x 1.4: + 2.05,0; - -2.05,0
SOT23 = smd 1 x 1.4: 1 -0.95,-1.1; 2 0.95,-1.1; 3 0,1.1
SOD123 = smd 1.4 x 1.4: A 1.9,0; C -1.9,0
SOD323-W = smd 1.5 x 1.2: A 1.45,0; C -1.45,0
MSOP-8 = smd 0.41 x 1.02: 1 -0.975,-2.4; 2 -0.325,-2.4; 3 0.325,-2.4; 4 0.975,-2.4; 5 0.975,2.4; 6 0.325,2.4; 7 -0.325,2.4; 8 -0.975,2.4
SOT223 = smd 1.499 x 2.007: 1 -2.261,-3.15; 2 0.025,-3.15; 3 2.311,-3.15 | smd 3.81 x 2.007: 4 0,3.15
DBZ_R-PDSO-G3 = smd 0.7 x 1: 1 -0.95,-1.1; 2 0.95,-1.1; 3 0,1.1
SO14 = smd 0.66 x 2.032: 1 -3.81,-3.073; 2 -2.54,-3.073; 3 -1.27,-3.073; 4 0,-3.073; 5 1.27,-3.073; 6 2.54,-3.073; 7 3.81,-3.073; 8 3.81,3.073; 9 2.54,3.073; 10 1.27,3.073; 11 0,3.073; 12 -1.27,3.073; 13 -2.54,3.073; 14 -3.81,3.073
SO08 = smd 0.6 x 2.2: 1 -1.905,-2.6; 2 -0.635,-2.6; 3 0.635,-2.6; 4 1.905,-2.6; 5 1.905,2.6; 6 0.635,2.6; 7 -0.635,2.6; 8 -1.905,2.6
SOIC16N = smd 0.6 x 2.2: 1 -4.445,-2.6; 2 -3.175,-2.6; 3 -1.905,-2.6; 4 -0.635,-2.6; 5 0.635,-2.6; 6 1.905,-2.6; 7 3.175,-2.6; 8 4.445,-2.6; 9 4.445,2.6; 10 3.175,2.6; 11 1.905,2.6; 12 0.635,2.6; 13 -0.635,2.6; 14 -1.905,2.6; 15 -3.175,2.6; 16 -4.445,2.6
WQP_PJ_301BM_WIDER = drill 0.7 pad 1.93 long: GND -4.8,-0.5 | drill 1.3 octagon: GND2 4.8,-0.5 | drill 0.5 pad 1.778 long: SW 0,-3.3; TIP 0,4.8
FIDUCIAL-1X2 = smd 1 x 1: 1 0,0
2X3_BOTTOM = smd 0.965 x 1.93: 1 -2.54,-3.3; 2 -2.54,3.3; 3 0,-3.3; 4 0,3.3; 5 2.54,-3.3; 6 2.54,3.3 | hole 1.1: -2.54,1.27; 0,1.27; 2.54,1.27; 2.54,-1.27; 0,-1.27; -2.54,-1.27
AVR_ICSP = drill 1.016 pad 1.88 octagon: 1 -1.27,5.08; 2 1.27,5.08; 3 -1.27,2.54; 4 1.27,2.54; 5 -1.27,0; 6 1.27,0; 7 -1.27,-2.54; 8 1.27,-2.54; 9 -1.27,-5.08; 10 1.27,-5.08
2X5-1.27 = drill 0.61 pad 1.067 octagon: 1 -1.27,3.81; 2 0,3.81; 3 -1.27,2.54; 4 0,2.54; 5 -1.27,1.27; 6 0,1.27; 7 -1.27,0; 8 0,0; 9 -1.27,-1.27; 10 0,-1.27
0603 = smd 0.85 x 0.7: 1 -0.9,0; 2 0.7,0
PTC-1206 = smd 1 x 1.8: 1 -1.4,0; 2 1.4,0
HC49UP = smd 5.334 x 1.93: 1 -4.826,0; 2 4.826,0
R0603 = smd 1 x 1.1: 1 -0.85,0; 2 0.85,0
ALPS_POT_VERTICAL_PS = drill 1 pad 1.88 square: P$1 -2.5,7; P$2 0,7; P$3 2.5,7 | drill 1.5 pad 2.54 octagon: P$4 -4.7,0; P$5 4.7,0
R1206 = smd 1.6 x 1.803: 1 -1.422,0; 2 1.422,0
ALPS_POT_VERTICAL = drill 1 pad 1.88 square: P$1 -2.5,6.7; P$2 0,6.7; P$3 2.5,6.7 | drill 2.2 pad 3.175 octagon: P$4 -4.4,0; P$5 4.4,0
TACTILE-PTH = drill 1.016 pad 1.88 round: 1 -3.251,2.261; 2 3.251,2.261; 3 -3.251,-2.261; 4 3.251,-2.261
PAD.03X.05 = smd 1.27 x 1.27: P$1 0,0
LQFP48 = smd 0.254 x 1: 1 -2.75,-4.25; 2 -2.25,-4.25; 3 -1.75,-4.25; 4 -1.25,-4.25; 5 -0.75,-4.25; 6 -0.25,-4.25; 7 0.25,-4.25; 8 0.75,-4.25; 9 1.25,-4.25; 10 1.75,-4.25; 11 2.25,-4.25; 12 2.75,-4.25; 25 2.75,4.25; 26 2.25,4.25; 27 1.75,4.25; 28 1.25,4.25; 29 0.75,4.25; 30 0.25,4.25; 31 -0.25,4.25; 32 -0.75,4.25; 33 -1.25,4.25; 34 -1.75,4.25; 35 -2.25,4.25; 36 -2.75,4.25 | smd 1 x 0.254: 13 4.25,-2.75; 14 4.25,-2.25; 15 4.25,-1.75; 16 4.25,-1.25; 17 4.25,-0.75; 18 4.25,-0.25; 19 4.25,0.25; 20 4.25,0.75; 21 4.25,1.25; 22 4.25,1.75; 23 4.25,2.25; 24 4.25,2.75; 37 -4.25,2.75; 38 -4.25,2.25; 39 -4.25,1.75; 40 -4.25,1.25; 41 -4.25,0.75; 42 -4.25,0.25; 43 -4.25,-0.25; 44 -4.25,-0.75; 45 -4.25,-1.25; 46 -4.25,-1.75; 47 -4.25,-2.25; 48 -4.25,-2.75

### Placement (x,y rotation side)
C1  52.7,104.78 270 top
C2  55.88,104.14 90 top
C3  25.4,97.79 90 top
C4  34.92,96.84 0 top
C5  15.56,93.34 90 top
C6  38.1,92.87 180 top
C7  41.27,92.87 0 top
C8  22.54,92.08 90 top
C9  22.54,88.9 270 top
C10  34.92,88.9 0 top
C11  55.88,87.95 270 top
C12  15.56,88.58 270 top
C13  52.7,85.41 270 top
C14  36.51,83.19 90 top
C15  38.1,83.19 90 top
C16  55.56,80.96 270 top
C17  37.78,79.06 180 top
C18  18.1,72.07 180 top
C19  21.91,72.07 0 top
C20  36.83,71.44 90 top
C21  41.59,71.44 90 top
C22  37.47,67.31 0 top
C23  40.96,67.31 180 top
C24  56.2,66 90 top
C25  18.41,59.69 180 top
C26  13.34,58.74 180 top
C27  21.59,58.1 0 top
C28  56.2,54.61 90 top
C29  17.14,53.66 90 top
C30  19.37,53.02 180 top
C31  39.69,52.7 180 top
C32  36.51,51.44 90 top
C33  22.54,45.72 90 top
C34  42.86,45.72 90 top
C35  5.08,40.01 0 top
C36  9.84,40.01 180 top
C37  48.9,40.01 0 top
C38  23.18,39.69 0 top
C39  48.9,38.73 180 top
C40  6.03,38.42 180 top
C41  9.84,38.42 180 top
C42  35.56,38.42 270 top
C43  53.34,38.42 180 top
C44  23.18,38.1 180 top
C45  49.53,36.2 90 top
C46  35.24,36.2 180 top
C47  33.34,30.8 90 top
C48  56.2,30 90 top
C49  8.89,28.89 0 top
C50  26.04,28.57 0 top
C51  33.34,28.57 180 top
C52  51.75,28.57 180 top
C53  5.4,28.26 270 top
C54  15.24,27.62 270 top
C55  43.5,27.62 270 top
C56  28.26,23.5 90 top
D1  5.71,86.04 270 top
D2  5.71,82.23 270 top
D3  55.24,70.17 180 top
D4  29.53,66.67 180 top
D5  29.53,63.5 180 top
D6  46.99,56.2 0 top
IC1  40.64,84.77 0 top
IC2  48.58,83.19 0 top
IC3  37.78,76.52 180 top
IC4  19.37,65.09 0 top
IC5  19.37,47.94 0 top
IC6  39.69,47.94 0 top
IC7  6.03,33.66 0 top
IC8  16.83,33.66 0 top
IC9  41.91,33.66 0 top
IC10  53.02,33.66 0 top
IC11  27.94,31.11 0 top
IC12  28.89,20 180 top
J1  7.62,20.95 90 top
J2  22.23,20.95 90 top
J3  36.83,20.95 90 top
J4  51.44,20.95 90 top
J5  7.62,6.35 90 top
J6  22.23,6.35 90 top
J7  36.83,6.35 90 top
J8  51.44,6.35 90 top
JP1  2.54,105.09 0 top
JP2  56.2,98.74 0 top
JP3  29.53,81.92 270 top
JP4  2.54,2.54 0 top
JP5  56.2,2.54 0 top
JP6  49.53,60.64 270 bottom
JP7  46.67,103.82 270 bottom
L1  55.88,100.65 0 top
P1  51.75,56.2 0 top
Q1  19.05,91.76 90 top
R1  23.81,96.84 90 top
R2  10.16,96.52 180 top
R3  48.9,96.52 180 top
R4  38.1,94.3 0 top
R5  41.27,94.3 180 top
R6  9.21,85.09 90 top
R7  9.21,81.28 270 top
R8  37.78,80.64 0 top
R9  18.1,76.2 0 top
R10  21.91,76.2 180 top
R11  55.88,75.88 180 top
R12  18.1,74.61 0 top
R13  21.91,74.61 180 top
R14  10.16,73.03 180 top
R15  48.9,73.03 180 top
R16  38.42,71.44 270 top
R17  40.01,71.44 270 top
R18  16.19,70.48 180 top
R19  21.91,70.48 0 top
R20  37.47,68.9 180 top
R21  40.96,68.9 0 top
R22  13.34,60.33 180 top
R23  21.59,59.69 0 top
R24  18.41,58.1 0 top
R25  9.84,56.83 0 top
R26  13.34,56.83 180 top
R27  29.53,56.83 180 top
R28  18.41,56.52 0 top
R29  40.01,56.83 270 top
R30  21.91,54.61 180 top
R31  24.77,50.48 270 top
R32  10.16,49.53 180 top
R33  48.9,49.53 180 top
R34  4.45,45.72 90 top
R35  54.13,45.56 270 top
R36  29.53,42.23 180 top
R37  19.37,39.37 270 top
R38  20.95,39.37 270 top
R39  45.09,39.37 270 top
R40  46.67,39.37 270 top
R41  12.38,39.05 270 top
R42  13.97,39.05 270 top
R43  37.15,39.05 270 top
R44  38.73,39.05 270 top
R45  24.77,35.88 270 top
R46  31.43,30.8 270 top
R47  22.54,28.57 180 top
R48  36.51,28.57 0 top
R49  12.06,27.94 270 top
R50  13.65,27.94 90 top
R51  18.41,27.78 90 top
R52  20,27.78 270 top
R53  39.05,27.78 270 top
R54  40.64,27.78 90 top
R55  45.09,27.62 90 top
R56  46.67,27.62 270 top
R57  29.84,23.5 270 top
R58  42.86,20 270 top
R59  28.89,17.46 0 top
R60  28.89,15.56 0 top
R61  14.92,7.3 270 top
R62  29.53,7.3 270 top
R63  44.13,3.49 90 top
R64  38.42,43.18 0 top
R65  16.51,43.18 180 top
SW1  23.81,102.55 0 top
SW2  35.24,102.55 0 top
SW3  29.53,70.8 180 top
TP1  2.86,89.85 0 top
TP2  2.86,78.74 0 top
U$1  [ROHS_BIG]  55.24,74.3 0 bottom
UC1  29.84,93.03 270 top

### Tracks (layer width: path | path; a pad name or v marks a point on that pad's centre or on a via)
+3V3  (via drill 0.6)
  Top 0.254: UC1.24 33.95,88.78 C10.1 32.38,90.59 32.38,93.19 | 32.38,93.19 32.38,95.57 33.66,96.84 C4.1 34.08,95.8 UC1.36 | 25.93,96.94 C3.1 | UC1.1 25.72,95.9 25.72,96.52 25.4,96.84 C3.1 | 25.93,96.94 26.27,97.28 UC1.48 | C3.1 25.18,97.16 24.77,97.16 24.23,97.69 R1.2 | 25.93,96.94 29.69,93.19 32.38,93.19
  Top 0.305: 51.12,100.65 51.12,95.89 53.02,93.98 53.02,88.27 52.7,87.95 C13.1 | 51.12,100.65 v51.12,104.46 51.17,104.51 | 51.12,100.65 L1.1
  Top 0.406: C10.1 34.08,87.84 34.61,87.31 34.61,85.72 | JP3.6 JP3.4 33.97,81.92 34.61,82.55 34.61,85.72 | 34.61,85.72 v35.24,85.72 | v46.35,84.14 48.58,84.14 | 48.58,84.14 50.48,84.14 52.6,86.26 C13.1 52.81,86.36 C11.+ | IC2.2 48.58,80.06 48.58,84.14
  Bottom 0.254: v51.12,104.46 48.9,106.68 43.5,106.68 42.86,106.05 JP7.1
  Bottom 0.406: v35.24,85.72 37.78,85.72 39.37,84.14 v46.35,84.14
+3V3_A  (via drill 0.6)
  Top 0.254: 51.44,89.56 R3.P$1 51.44,89.48 | C9.1 C8.1 22.64,91.12 23.18,91.12 23.83,91.78 UC1.9 | 12.7,89.56 R2.P$1 | D1.2 | 4.45,81.11 D2.2 | 19.27,61.91 IC4.4 19.37,65.41 18.41,66.36 17.14,66.36 13.65,62.87 v12.7,62.87 | 45.09,78.11 49.53,73.66 49.53,68.9 51.4,67.03 R15.P$1
  Top 0.305: 51.44,89.56 51.44,91.44 50.16,92.71 50.16,105.41 | 50.16,105.41 48.9,106.68 15.56,106.68 7.94,99.06 7.94,94.3 | 51.44,89.48 51.44,88.58 50.8,87.95 46.04,87.95 45.09,87 45.09,78.11 | v20.85,91.22 C8.1 | 12.7,89.56 12.7,91.12 9.53,94.3 7.94,94.3 | 1.27,85.09 D1.2 | 50.16,105.41 52.49,105.41 C1.1 52.82,105.74 C2.+ 56.82,105.74 57.47,105.09 57.47,100.97 57.15,100.65 L1.2 | v35.56,80.64 R8.1 36.93,81.17 C15.1 | C15.1 C14.1 | C15.1 38.14,82.37 IC1.1 | C25.1 19.37,59.79 IC4.4 | R14.P$1 12.66,67.03 12.38,67.31 12.38,69.53 4.45,77.47 1.91,77.47 1.27,78.11 1.27,81.28 | 7.94,94.3 4.13,94.3 1.27,91.44 1.27,85.09 | 1.27,81.28 1.27,85.09 | 4.45,81.11 4.28,81.28 1.27,81.28
  Bottom 0.305: v35.56,80.64 38.1,83.19 48.58,83.19 51.4,86 R3.P$1 | R14.P$1 12.7,65.98 v12.7,62.87 | v20.85,91.22 20.75,91.12 13.65,91.12 12.66,90.13 R2.P$1
ADC_AUX_1  (via drill 0.6)
  Top 0.254: C26.2 R22.2 12.7,60.54 12.38,60.86 12.38,60.96 12.7,61.28 15.24,61.28 15.56,61.59 IC4.1 15.56,63.18 v17.78,65.41 | v29.21,91.76 29.59,91.37 UC1.18
  Bottom 0.254: v29.21,91.76 28.26,92.71 26.99,92.71 26.35,92.08 26.35,90.81 25.72,90.17 24.77,90.17 17.78,83.19 17.78,78.11 17.14,77.47 17.14,68.58 17.78,67.94 v17.78,65.41
ADC_AUX_2  (via drill 0.6)
  Top 0.254: C27.2 R23.2 22.54,59.79 22.54,60.33 23.18,60.96 IC4.7 23.18,63.5 21.27,65.41 v20.95,65.41 | v27.94,90.49 28.26,90.49 28.59,90.15 UC1.16
  Bottom 0.254: v27.94,90.49 26.35,88.9 25.4,88.9 19.05,82.55 19.05,71.75 17.78,70.48 17.78,68.9 18.41,68.26 18.41,66.36 19.37,65.41 v20.95,65.41
ADC_CV_1
  Top 0.254: UC1.14 27.59,87.92 27.3,87.63 26.04,87.63 25.4,87 25.4,85.88 21.43,81.92 15.24,81.92 13.65,83.5 9.53,83.5 9.21,83.82 R6.1 8.62,84.24 D1.3
ADC_CV_2  (via drill 0.6)
  Top 0.254: v24.45,83.19 23.5,83.19 21.75,81.44 14.92,81.44 14.13,82.23 9.31,82.23 R7.1 6.92,82.13 D2.3 | v26.35,86.68 26.67,87 27.62,87 28.09,87.47 UC1.15
  Bottom 0.254: v24.45,83.19 26.35,85.09 v26.35,86.68
ADC_IN_1  (via drill 0.6)
  Top 0.254: IC4.14 15.56,69.22 15.34,69.43 R18.2 15.34,70.91 16.51,72.07 C18.2 17.25,72.49 v18.1,73.34 | v27.3,91.76 27.94,91.76 29.09,90.6 UC1.17
  Bottom 0.254: v27.3,91.76 26.99,91.44 26.99,90.49 26.04,89.53 25.08,89.53 18.41,82.87 18.41,77.79 18.1,77.47 v18.1,73.34
ADC_IN_2  (via drill 0.6)
  Top 0.254: v29.21,87.31 29.53,87.31 30.09,87.88 UC1.19 | IC4.8 23.18,69.53 22.86,69.85 22.86,70.38 R19.2 C19.2 22.76,72.61 v23.5,73.34
  Bottom 0.254: v29.21,87.31 28.26,88.27 25.72,88.27 19.68,82.23 19.68,74.61 20.95,73.34 v23.5,73.34
AMOUNT_1  (via drill 0.6)
  Top 0.254: UC1.13 26.97,88.9 25.4,88.9 24.92,88.42 24.92,86.2 21.11,82.39 15.56,82.39 13.49,84.45 v10.79,84.45 | R14.P$2 10.16,65.09 10.79,64.45 13.65,64.45 14.13,64.93 14.13,67.47 13.34,68.26 13.34,70.17 10.79,72.71 v10.79,77.79
  Bottom 0.254: v10.79,77.79 v10.79,84.45
AMOUNT_2  (via drill 0.6)
  Top 0.254: R15.P$2 48.9,73.03 44.45,77.47 44.45,93.66 v41.27,96.84 | UC1.10 24.29,91.28 23.5,90.49 23.5,87.15 20.16,83.82 16.51,83.82 14.61,85.72 14.61,93.66 13.02,95.25 13.02,97.16 18.41,102.55 39.69,102.55 40.01,102.87 40.32,102.87 v40.64,103.19
  Bottom 0.254: v40.64,103.19 40.96,102.87 40.96,97.16 v41.27,96.84
AREF_2.5
  Top 0.254: IC1.2 40.31,81.27 39.69,80.64 R8.2
  Top 0.305: R8.2 C17.1 38.73,78.96 IC3.1
AREF_+5
  Top 0.254: R59.1 26.67,17.46 25.52,18.61 J2.SW
AREF_+10  (via drill 0.6)
  Top 0.254: R57.2 C56.1 | R57.2 IC12.1 29.74,21 R59.2 | R57.2 29.9,22.7 | R59.2 33.02,17.46 33.66,18.1 v41.27,18.1 42.55,18.1 42.86,18.41 R58.2 | R60.2 R59.2 | v44.13,11.11 R63.2
  Bottom 0.254: v44.13,11.11 41.27,13.97 v41.27,18.1
AREF_-10  (via drill 0.6)
  Top 0.254: R24.1 v16.19,58.1 16.19,57.47 15.56,56.83 R26.1 | 19.37,41.27 v18.1,41.27 | v12.38,76.52 12.7,76.83 15.88,76.83 16.51,76.2 R9.1 17.25,76.94 17.46,77.15 22.23,77.15 22.54,76.83 22.54,76.42 R10.1 | 38.84,39.9 R44.1 38.73,40.32 v37.78,41.27 | R37.1 19.37,41.27 | 19.37,41.27 22.23,41.27 22.86,41.91 22.86,42.7 25.24,45.09 35.56,45.09 v35.88,44.77 37.47,43.18 R64.1 | IC11.2 28.96,29.95 R46.2 C47.1 33.39,30 33.55,29.84 34.61,29.84 34.92,30.16 v35.88,30.16 | v18.73,43.18 R65.1
  Bottom 0.254: v18.1,41.27 18.1,43.18 | 18.1,43.18 18.1,49.53 14.29,53.34 14.29,58.1 | v35.88,44.77 37.78,42.86 v37.78,41.27 37.78,31.11 36.83,30.16 v35.88,30.16 | v12.38,76.52 11.75,75.88 11.75,71.12 14.29,68.58 14.29,58.1 | 14.29,58.1 v16.19,58.1 | 18.1,43.18 v18.73,43.18
BARGRAPH_CS  (via drill 0.6)
  Top 0.254: v29.53,77.47 27.3,77.47 26.23,78.55 JP3.5 | v29.37,95.57 29.59,95.79 UC1.43
  Bottom 0.254: v29.53,77.47 29.53,85.25 30.8,86.52 30.8,94.14 v29.37,95.57 29.21,95.57
BARGRAPH_MOSI
  Top 0.254: UC1.21 31.09,87.45 29.37,85.72 26.99,85.72 26.23,84.97 JP3.1
BARGRAPH_SCK
  Top 0.254: UC1.22 31.59,87.16 29.53,85.09 29.53,83.82 28.89,83.19 26.67,83.19 26.23,82.74 JP3.3
DAC_1
  Top 0.254: R20.2 C22.1 36.62,66.14 35.56,65.09 26.67,65.09 25.4,63.82 25.4,59.69 27.3,57.78 27.3,55.88 26.04,54.61 R30.1
DAC_2
  Top 0.254: R21.2 C23.1 41.91,67.21 41.91,65.41 40.01,63.5 R29.1
DAC_MOSI
  Top 0.254: IC1.7 40.32,87.17 40.32,86.2 39.37,86.2 38.73,86.84 38.73,90.01 37.47,91.28 35.4,91.28 34.91,91.78 UC1.28
DAC_SCK
  Top 0.254: IC1.6 40.96,87.17 40.96,86.04 40.64,85.72 39.05,85.72 38.26,86.52 38.26,89.69 37.17,90.78 UC1.26
DAC_SS
  Top 0.254: IC1.5 41.59,87.15 41.59,85.88 40.96,85.25 38.73,85.25 37.78,86.2 37.78,89.38 36.88,90.28 UC1.25
FB_CURRENT1
  Top 0.254: IC8.10 20,37.15 20.95,38.1 R38.2 R37.2
FB_CURRENT2
  Top 0.254: R41.2 R42.2 13.97,37.78 13.65,37.47 IC8.15
FB_CURRENT3
  Top 0.254: IC9.10 R39.2 R40.2
FB_CURRENT4
  Top 0.254: R43.2 R44.2 IC9.15
GND  (via drill 0.6)
  Top 0.254: 27.62,96.2 27.62,97.25 UC1.47 27.59,98.08 v28.57,99.06 29.09,98.54 UC1.44 | UC1.35 34.79,95.28 35.77,96.26 C4.2 | C8.2 22.64,93.03 | v23.81,92.71 24.25,92.28 UC1.8 | UC1.20 30.59,89.62 30.68,89.71 31.8,89.71 32.11,89.41 32.11,88.79 UC1.23 32.09,87.76 v32.7,87.15 | IC4.3 18.1,60.96 17.57,60.43 C25.2 | C45.2 | C45.2 49.53,37.78 49.74,38 C39.1
  other vias: 37.31,97 55.88,93.34 57.47,82.55 43.18,91.12 36.67,87.31 35.88,92.39 17.14,92.39 23.97,99.22 2.86,83.19 2.86,87 15.88,59.69 22.54,30.48 42.23,25.72 49.85,30.8 7.62,40.01 13.02,55.24 44.45,21.27 56.2,27.62 20.64,43.18 39.05,65.41 34.61,52.39 42.86,43.18 52.39,54.29 26.99,23.81 13.34,51.75 42.86,51.44 40.16,88.9 41.59,73.98 36.83,73.98 52.7,102.23 48.58,77.79 42.07,78.74 11.11,61.91 18.41,64.14 19.68,70.17 22.86,50.8 6.99,80.33 20.95,88.9 16.83,79.06 20.95,79.06 4.13,68.58 7.62,68.58 4.13,58.42 7.62,58.42 20.95,56.52 2.54,15.88 1.27,45.72 1.27,55.88 2.86,66.04 2.86,75.56 2.86,96.52 31.11,74.61 12.06,81.28 24.13,81.28 53.66,41.27 16.83,26.35 30.8,28.57 34.61,32.07 27.94,43.18 15.88,54.93 27.94,46.04 27.94,38.1 33.34,38.73 28.57,28.57 17.14,89.53
  pour Bottom: 0,107.63 0,0 58.74,0 58.74,107.63
  pour Top (isolate 0.203): 0,107.63 0,0 58.74,0 58.74,107.63
IN_1  (via drill 0.6)
  Top 0.254: R42.1 14.07,40.01 v15.4,40.01 | v15.24,75.88 16.51,74.61 R12.1 | v9.53,73.98 9.53,77.79 10.48,78.74 v15.24,78.74 | v12.06,52.39 v5.71,52.39
  Bottom 0.254: J2.TIP 17.43,24.17 15.24,26.35 15.24,37.15 14.61,37.78 14.61,39.21 v15.4,40.01 15.4,44.29 12.06,47.62 v12.06,52.39 | v15.24,78.74 14.92,78.42 14.92,76.2 v15.24,75.88 | v5.71,52.39 5.71,69.53 9.53,73.34 v9.53,73.98
IN_2  (via drill 0.6)
  Top 0.254: v39.05,24.13 38.1,23.18 32.7,23.18 32.03,22.5 J3.TIP | v32.07,10.16 34.29,7.94 34.29,5.08 32.7,3.49 24.45,3.49 23.81,4.13 19.68,4.13 19.05,3.49 10.48,3.49 4.76,9.21 v4.76,11.43 | v2.22,63.82 13.81,63.82 14.76,64.77 14.76,67.79 13.97,68.58 | R13.1 23.5,74.61 23.81,74.93 23.81,76.83 22.86,77.79 17.14,77.79 16.83,77.47 12.06,77.47 11.43,76.83 11.43,73.03 13.97,70.48 13.97,68.58 | v41.59,38.73 43.08,40.22 R39.1 | 13.97,68.58
  Bottom 0.254: v41.59,38.73 39.05,36.2 v39.05,24.13 | J3.TIP 32.07,20.92 v32.07,10.16 | v4.76,11.43 4.76,22.54 2.22,25.08 v2.22,63.82
JTCK  (via drill 0.6)
  Top 0.254: UC1.37 32.59,97.68 32.86,97.95 40.16,97.95 42.55,100.33 43.81,100.33 v44.13,100.01
  Bottom 0.254: v44.13,100.01 JP7.4
JTDI  (via drill 0.6)
  Top 0.254: UC1.38 32.09,97.98 32.54,98.42 39.69,98.42 42.23,100.97 44.45,100.97 45.09,100.33 v46.67,100.33
  Bottom 0.254: v46.67,100.33 JP7.8
JTDO  (via drill 0.6)
  Top 0.254: UC1.39 31.59,98.27 32.23,98.9 39.21,98.9 41.91,101.6 45.09,101.6 v45.4,101.28
  Bottom 0.254: v45.4,101.28 JP7.6
JTMS  (via drill 0.6)
  Top 0.254: UC1.34 35.09,94.78 36.2,95.89 39.05,95.89 42.55,99.38 v42.86,99.38
  Bottom 0.254: v42.86,99.38 JP7.2
N$1
  Top 0.254: R31.2 25.27,50.13 R27.P$3
N$2
  Top 0.254: C30.1 20.22,52.28 20,52.07 IC5.6 20,49.21 19.05,48.26 17.14,48.26 15.66,46.77 R65.2 | C30.1 20.11,53.13 | IC8.12 17.46,37.78 16.51,38.73 16.51,41.27 15.66,42.12 R65.2 | R30.2 20.22,53.77 C30.1 | R32.P$1 12.68,42.55 13.97,42.55 14.61,43.18 R65.2
N$3
  Top 0.254: R63.1 44.23,2.54 46.67,2.54 50.48,6.35 J8.SW
N$4
  Top 0.254: R40.1 46.77,40.32 47.09,40.01 C37.1
N$5
  Top 0.254: C38.1 21.91,39.69 21.38,40.22 R38.1
N$7
  Top 0.254: UC1.5 24.97,93.78 24.13,94.61 21.59,94.61 19.62,96.58 Q1.2 18.8,96.58 16.51,94.3 15.66,94.3 C5.2
N$8
  Top 0.254: UC1.6 24.52,93.28 23.81,93.98 21.27,93.98 19.05,91.76 19.05,87.95 | 19.05,87.95 Q1.1 | C12.2 15.77,87.95 19.05,87.95
N$9  (via drill 0.6)
  Top 0.254: IC6.6 40.32,51.75 40.54,51.97 C31.1 | C31.1 40.42,52.82 40.64,53.03 40.64,53.34 40.01,53.98 R29.2 | C31.1 44.13,52.7 46.35,50.48 46.35,46.67 47.31,45.72 v50.48,45.72 | IC9.13 41.27,37.47 40.64,38.1 40.64,40.96 | R33.P$1 51.44,42.49 51.44,41.59 50.96,41.12 42.07,41.12 | 42.07,41.12 | 42.07,41.12 41.91,40.96 40.64,40.96 | R64.2 39.37,43.08 39.37,42.23 40.64,40.96
  Bottom 0.254: v50.48,45.72 51.4,44.81 R33.P$1
N$10
  Top 0.254: C36.1 10.79,39.9 R41.1
N$11
  Top 0.254: IC5.1 IC5.2
N$12
  Top 0.254: R60.1 27.94,15.46 27.94,4.76 27.3,4.13 24.77,4.13 24.13,4.76 19.05,4.76 18.41,4.13 12.06,4.13 10.92,5.27 J5.SW
N$13
  Top 0.254: J5.TIP 2.82,12.03 4.76,13.97 4.76,22.86 2.54,25.08 2.54,33.18 2.86,33.5 2.86,42.23 4.45,43.81 R34.1
N$14  (via drill 0.6)
  Top 0.254: C43.1 54.19,38 53.66,37.47 IC10.6 53.66,34.61 53.34,34.29 36.67,34.29 v36.2,34.77 | IC9.4 41.27,32.23 40.96,32.54 36.67,32.54 v36.2,32.07
  Bottom 0.254: v36.2,32.07 v36.2,34.77
N$15  (via drill 0.6)
  Top 0.254: v29.53,46.99 26.35,46.99 22.23,42.86 22.23,42.55 21.91,42.23 17.78,42.23 17.14,41.59 17.14,39.05 18.73,37.47 IC8.11
  Bottom 0.254: v29.53,46.99 R27.P$2
N$16  (via drill 0.6)
  Top 0.254: IC10.7 52.49,36.36 C43.2 52.39,38.52 v52.39,40.01 | 45.4,24.13 41.27,24.13 39.05,26.35 R53.2 | R62.1 29.53,10.48 33.66,14.61 42.55,14.61 45.4,17.46 45.4,24.13 | 45.4,24.13 v46.35,24.13
  Bottom 0.254: v52.39,40.01 50.16,40.01 49.21,39.05 47.31,39.05 46.35,38.1 v46.35,24.13
N$17
  Top 0.254: J7.TIP 31.93,6.45 R62.2
N$18
  Top 0.254: R45.2 25.27,35.53 R36.P$3
N$19
  Top 0.254: C42.1 35.66,39.37 36.2,39.37 36.73,39.9 R43.1
N$21
  Top 0.406: IC2.3 50.91,80.01 52.39,80.01 53.48,78.91 | 53.48,78.91 C16.+ | R11.2 54.29,76.05 54.29,76.83 53.48,77.64 53.48,78.91
N$23
  Top 0.254: R34.2 4.55,46.67 7.62,46.67 10.16,44.13 R32.P$2
N$24
  Top 0.254: R33.P$2 48.9,43.5 49.53,44.13 52.7,44.13 53.28,44.71 R35.2
N$25  (via drill 0.6)
  Top 0.254: v56.83,46.67 56.83,33.34 57.15,33.02 57.15,15.24 55.24,13.34 49.53,13.34 46.63,10.44 J8.TIP | v52.55,46.67 52.81,46.41 R35.1
  Bottom 0.254: v56.83,46.67 v52.55,46.67
N$26  (via drill 0.6)
  Top 0.254: IC7.6 6.67,35.08 7.46,34.29 21.91,34.29 v22.54,34.92 | IC8.5 17.46,32.23 17.78,32.54 22.23,32.54 22.54,32.23 v22.54,32.07
  Top 0.305: IC7.6 6.67,37.47 6.88,37.68 C40.1
  Bottom 0.254: v22.54,34.92 v22.54,32.07
N$27
  Top 0.254: IC7.7 5.4,34.92 5.08,34.61 3.81,34.61 3.49,34.29 3.49,33.34 3.17,33.02 3.17,25.4 5.4,23.18 11.11,23.18 12.7,24.77 14.92,24.77 | 14.92,24.77 18.73,24.77 20,26.04 R52.2 | 14.92,17.78 14.92,24.77
  Top 0.305: IC7.7 5.4,37.47 5.18,37.68 C40.2 | R61.1 14.92,17.78
N$28
  Top 0.254: IC6.1 IC6.2
N$29
  Top 0.254: 40.01,35.56 IC9.14 40.01,40.64 38.42,42.23 36.99,42.23 34.92,40.16 32.86,40.16 29.53,36.83 R36.P$2
N$43
  Top 0.254: R58.1 42.76,20.95 J3.SW
N$51  (via drill 0.6)
  Top 0.254: IC8.13 16.19,35.08 15.88,34.77 11.91,34.77 11.43,35.24 v11.11,35.24 | IC8.2 R50.2 R49.1 11.21,28.79 11.11,28.89 v11.11,31.11
  Bottom 0.254: v11.11,31.11 v11.11,35.24
N$56  (via drill 0.6)
  Top 0.406: JP6.2 JP6.1 | v51.44,70.17 D3.A
  Bottom 0.406: JP6.1 44.45,67.31 47.31,70.17 v51.44,70.17
N$64
  Top 0.305: P1.2 53.34,56.38 53.34,58.1 JP6.10
  Top 0.406: JP6.10 JP6.9
N$65
  Top 0.254: J1.TIP 2.86,20.99 2.86,22.54 1.27,24.13 1.27,33.66 1.59,33.97 1.59,42.86 2.86,44.13 2.86,53.02 6.67,56.83 R25.1
N$66
  Top 0.254: IC4.6 21.91,60.96 20.74,59.79 R23.1 C27.1 R24.2 R28.2
N$67
  Top 0.254: R28.1 16.19,56.52 13.65,53.98 4.76,53.98 3.49,52.7 3.49,43.81 2.22,42.55 2.22,33.66 1.91,33.34 1.91,24.77 4.13,22.54 4.13,14.29 1.27,11.43 1.27,4.76 1.91,4.13 5.08,4.13 6.03,3.17 9.84,3.17 10.16,2.86 19.37,2.86 20,3.49 23.5,3.49 24.13,2.86 33.02,2.86 33.34,3.17 41.27,3.17 42.55,4.45 42.55,11.75 46.63,15.84 J4.TIP
N$68
  Top 0.254: IC4.13 16.83,69.22 17.04,69.43 R18.1 18.1,70.48 18.95,71.33 C18.1 19.05,72.17 19.05,74.3 18.95,74.4 R12.2 R9.2
N$69
  Top 0.254: IC4.2 16.83,60.96 16.51,60.64 15.24,60.64 14.92,60.33 R22.1 C26.1 14.19,58.53 R26.2 R25.2
N$70
  Top 0.254: IC1.4 41.59,82.35 41.59,80.64 40.32,79.38 40.32,73.66 40.01,73.34 R17.1
N$71
  Top 0.254: R10.2 R13.2 C19.1 R19.1 21.27,70.27 21.27,69.85 21.91,69.22 IC4.9
N$72
  Top 0.254: IC1.3 40.96,82.36 40.96,80.96 39.69,79.69 39.69,74.3 38.42,73.03 R16.1
N$73
  Top 0.254: 40.01,69 R21.1 40.11,70.48 R17.2 C21.1
N$74
  Top 0.254: C20.1 R16.2 38.31,70.48 R20.1
N$75  (via drill 0.6)
  Top 0.254: IC9.7 R55.2 R56.1 47.52,28.47 47.94,28.89 v47.94,30 | IC9.12 42.55,35.08 42.86,34.77 47.31,34.77 47.78,35.24 v47.94,35.24
  Bottom 0.254: v47.94,30 v47.94,35.24
N$76
  Top 0.254: IC9.5 42.55,32.23 42.86,32.54 52.07,32.54 52.39,32.23 IC10.2 52.39,29.53 52.6,29.31 C52.1
N$77
  Top 0.254: IC9.2 38.73,29.53 39.05,29.21 R53.1 | R48.2 37.47,28.47 37.57,28.57 38.1,28.57 38.16,28.63 R53.1 | R53.1 R54.2
N$78
  Top 0.254: IC10.1 51.12,29.53 50.8,29.21 50.8,28.68 C52.2 50.9,28.04 49.53,26.67 46.67,26.67 | 46.67,26.67 46.67,26.04 45.4,24.77 41.59,24.77 40.64,25.72 R54.1 | 46.67,26.67 R56.2
N$79
  Top 0.254: IC8.4 16.19,32.38 16.03,32.54 5.71,32.54 5.4,32.23 IC7.2 C53.1
N$81
  Top 0.254: R55.1 43.5,28.36 C55.1
N$82
  Top 0.254: C51.1 R48.1
N$83
  Top 0.254: 12.06,25.4 10.48,23.81 7.3,23.81 5.4,25.72 C53.2 4.66,27.41 4.13,27.94 IC7.1 | 12.06,25.4 R49.2 | 12.06,25.4 17.78,25.4 18.41,26.04 R51.1
N$84
  Top 0.254: R52.1 R51.2 | R52.1 IC8.7 | R47.2 21.64,28.63 R52.1
N$85
  Top 0.254: 15.24,28.36 C54.1 15.04,28.47 R50.1
N$86
  Top 0.254: R47.1 C50.1
N$87
  Top 0.254: R61.2 15.03,6.35 J6.TIP
N$90
  Top 0.254: R5.1 41.91,94.51 41.91,94.93 41.59,95.25 36.35,95.25 34.88,93.78 UC1.32
N$93
  Top 0.254: R4.1 36.2,94.3 35.17,93.28 UC1.31
PWM_CUTOFF_1  (via drill 0.6)
  Top 0.254: R4.2 C6.1 39.05,92.77 39.05,92.08 43.18,87.95 43.18,76.83 46.35,73.66 46.35,70.17 43.81,67.63 43.81,64.77 42.23,63.18 v42.23,56.52 | IC8.3 14.92,29.84 15.24,29.53 16.83,29.53 | 16.83,29.53 18.41,29.53 18.73,29.84 IC8.6 | 16.83,29.53 16.83,28.42 17.46,27.78 20.8,27.78 21.11,27.46 24.92,27.46 v25.4,26.99 | v26.67,40.01 v29.21,40.01
  Bottom 0.254: v42.23,56.52 38.1,56.52 35.88,54.29 35.88,50.8 29.53,44.45 29.53,40.32 v29.21,40.01 | v25.4,26.99 25.72,27.3 25.72,31.43 25.4,31.75 25.4,38.73 v26.67,40.01
PWM_CUTOFF_2  (via drill 0.6)
  Top 0.254: R5.2 C7.1 40.32,92.77 40.32,91.76 43.81,88.27 43.81,77.15 46.99,73.98 46.99,69.85 44.45,67.31 44.45,64.45 42.86,62.87 42.86,58.1 43.81,57.15 43.81,55.56 47.62,51.75 v47.62,47.31 | IC9.6 43.81,29.84 43.5,29.53 42.07,29.53 | 42.07,29.53 40.32,29.53 40.01,29.84 IC9.3 | 42.07,29.53 v42.07,28.57
  Bottom 0.254: v47.62,47.31 47.62,46.35 45.09,43.81 45.09,32.54 42.07,29.53 v42.07,28.57
RESET  (via drill 0.6)
  Top 0.254: v22.86,101.6 23.18,101.92 40.01,101.92 40.32,102.23 46.99,102.23 47.94,103.19 JP7.10 | v27.3,94.3 27.3,93.03 27.05,92.78 UC1.7 | R1.1 23.6,96.2 v22.23,96.2
  Bottom 0.254: v27.3,94.3 25.4,96.2 v22.23,96.2 22.86,96.84 v22.86,101.6
SHAPE_1
  Top 0.254: UC1.12 25.19,90.28 24.45,89.53 24.45,86.52 20.8,82.87 15.88,82.87 13.65,85.09 13.65,86.68 12.86,87.47 10.64,87.47 10.16,87.95 R2.P$2
SHAPE_2
  Top 0.254: R3.P$2 48.9,100.97 49.53,101.6 49.53,105.09 48.58,106.05 42.23,106.05 39.37,103.19 17.78,103.19 12.38,97.79 12.38,94.93 14.13,93.19 14.13,85.41 16.19,83.34 20.48,83.34 23.97,86.84 23.97,90.01 24.74,90.78 UC1.11
SW_METER  (via drill 0.6)
  Top 0.254: SW3.4 SW3.3 | 30.09,96.59 UC1.42 30.09,96.27 v30.8,95.57
  Bottom 0.254: v30.8,95.57 31.43,94.93 31.43,93.98 31.43,86.04 32.23,85.25 32.23,73.82 32.78,73.27 SW3.3
SW_MODE_1
  Top 0.254: UC1.41 30.59,98.63 28.89,100.33 27.1,100.33 SW1.4 SW1.3
SW_MODE_2
  Top 0.254: SW2.4 SW2.3 31.09,99.4 UC1.40
VCA_CONTROL_1  (via drill 0.6)
  Top 0.254: C30.2 18.52,52.28 18.73,52.07 IC5.7 18.73,49.21 18.41,48.9 16.83,48.9 15.24,47.31 v14.61,47.31 | C30.2 18.73,53.24 | IC8.14 14.92,37.78 v15.56,38.42 | v19.05,54.29 18.52,53.76 C30.2 | v12.06,86.04 9.31,86.04 R6.2 9.21,87 8.26,87.95 4.76,87.95 TP1.P$1 | v23.81,52.7 32.07,52.7 | R27.P$1 32.07,50.17 32.07,52.7 | D5.C 31.11,63.36 31.11,54.61 32.07,53.66 32.07,52.7
  Bottom 0.254: v12.06,86.04 14.13,83.98 14.13,75.09 13.02,73.98 13.02,72.39 15.88,69.53 15.88,60.96 19.05,57.78 v19.05,54.29 20.64,52.7 v23.81,52.7 | v14.61,47.31 14.61,46.04 16.19,44.45 16.19,40.64 16.51,40.32 16.51,39.37 v15.56,38.42
VCA_CONTROL_2  (via drill 0.6)
  Top 0.254: IC6.7 39.05,51.75 38.84,51.97 C31.2 38.73,52.81 v38.73,54.93 38.73,59.69 36.51,61.91 v34.61,61.91 | IC9.11 43.81,37.47 43.5,37.78 v43.5,38.42 | v33.34,46.04 35.56,46.04 36.83,47.31 v38.73,47.31 | D4.C v34.61,66.67 34.92,66.99 34.92,73.98 33.02,75.88 26.67,75.88 22.23,80.33 9.31,80.33 R7.2 9.21,79.69 8.26,78.74 TP2.P$1
  Bottom 0.254: v34.61,61.91 v34.61,66.67 | v33.34,46.04 31.11,43.81 31.11,38.1 32.03,37.19 R36.P$1 | v43.5,38.42 43.5,40.96 38.73,45.72 v38.73,47.31 v38.73,54.93
VCC  (via drill 0.6)
  Top 0.254: v29.84,26.99 R57.1 | 30.16,33.81 33.97,33.81 | 33.97,33.81 34.92,33.81 | 34.92,33.81 v54.45,33.81 | v51.12,38.26 IC10.8 50.44,36.26 C45.1 | v6.19,34.29 6.67,33.81 | v9.21,36.51 10.69,38 | 10.69,38 C41.1 | IC8.16 12.12,36.51 12.06,36.51 10.69,37.88 10.69,38 | 30.16,33.81 | 30.16,33.81 v30.16,33.02 | 36.55,50.54 36.51,50.5 v36.51,49.21 | 33.97,33.81 v33.97,34.29 | IC6.8 37.74,50.59 C32.1 | 34.92,33.81 34.92,35.03 C46.1 36.15,36.26 IC9.16 | 6.67,33.81 | 6.67,33.81 30.16,33.81 | 57.47,62.87 57.47,67.63 | 57.47,67.63 57.47,68.58 57.15,68.9 D3.C | C24.+ 56.22,67.63 57.47,67.63
  Top 0.305: IC7.8 4.13,38.42 | 4.13,38.42 4.13,39.37 4.23,39.47 C35.1 | 4.13,38.42 v3.81,38.42 | v55.88,41.27 55.88,47.31 56.52,47.94 56.52,50.8 57.47,51.75 57.47,62.87 | IC5.8 17.46,51.75 17.14,52.07 C29.1 17.04,52.7 16.51,52.7 v15.88,53.34 | v20,47.62 20.64,47.62 21.59,48.58 33.66,48.58 35.66,50.59 C32.1 36.55,50.54 | 57.16,70.15 57.12,70.11
  Top 0.406: IC8.16 12.32,36.2 | 57.16,70.15 D3.C 57.15,74.61 57.3,74.76 R11.1
  Bottom 0.254: v30.16,33.02 29.84,32.7 v29.84,26.99 | v51.12,38.26 51.12,34.61 51.91,33.81 v54.45,33.81 55.09,33.81 55.88,34.61 v55.88,41.27 | v3.81,38.42 3.81,36.2 5.71,34.29 v6.19,34.29 6.99,34.29 v9.21,36.51 | v36.51,49.21 36.51,47.94 31.75,43.18 31.75,38.73 33.97,36.51 v33.97,34.29
  Bottom 0.305: v20,47.62 20,50.48 17.14,53.34 v15.88,53.34
VEE  (via drill 0.6)
  Top 0.254: v56.2,32.7 53.18,32.7 52.7,33.18 32.23,33.18 31.43,32.38 R46.1 29.95,31.65 28.42,33.18 24.13,33.18 | IC9.9 46.41,36.2 46.67,36.2 v47.94,37.47 48.05,37.57 C39.2 | v4.6,33.18 24.13,33.18 | 24.13,33.18 v24.13,30.8 | v23.81,46.35 22.76,46.35 C33.2 21.49,46.57 21.27,46.35 | v23.18,36.83 22.33,37.68 C44.2 22.33,37.57 21.27,36.51 IC8.9 | 21.27,46.35 21.27,47.31 21.91,47.94 36.51,47.94 37.15,48.58 39.37,48.58 40.32,47.62 42.55,47.62 42.86,47.31 C34.2 42.76,46.67 41.59,46.67 IC6.4 | 21.27,46.35 IC5.4 | v9.21,30.8 9.74,30.27 C49.2 9.74,29 7.94,30.8 IC7.4
  Top 0.305: 54.99,31.11 IC10.4 56,31.05 C48.2 v56.2,32.7 56.2,39.37 54.93,40.64 54.93,41.91 55.24,42.23 55.24,47.94 55.88,48.58 55.88,51.44 56.2,51.75 C28.- 56.19,53.02 51.75,53.02 50.35,54.42 P1.1 D6.A
  Bottom 0.254: v47.94,37.47 49.21,37.47 50.48,36.2 50.48,34.29 52.07,32.7 v56.2,32.7 | v4.6,33.18 6.99,30.8 v9.21,30.8 | v23.81,46.35 23.5,46.35 22.54,45.4 22.54,37.47 v23.18,36.83 24.13,35.88 v24.13,30.8

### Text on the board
tPlace: TP1 | TP2
bPlace: Red stripe
tNames: cc-by-sa Olivier Gillet, 2014. v0.5 | Streams
bNames: Streams | cc-by-sa Olivier Gillet, 2014. v0.5 | +12V | GND | -12V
